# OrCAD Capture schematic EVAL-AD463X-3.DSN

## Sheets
1 PAGE1: size C; title: PRECISION SAR, DUAL ADC; rev: REV03; note: EVAL-AD463X_REV03; note: DIFFERENTIAL DUAL ADC
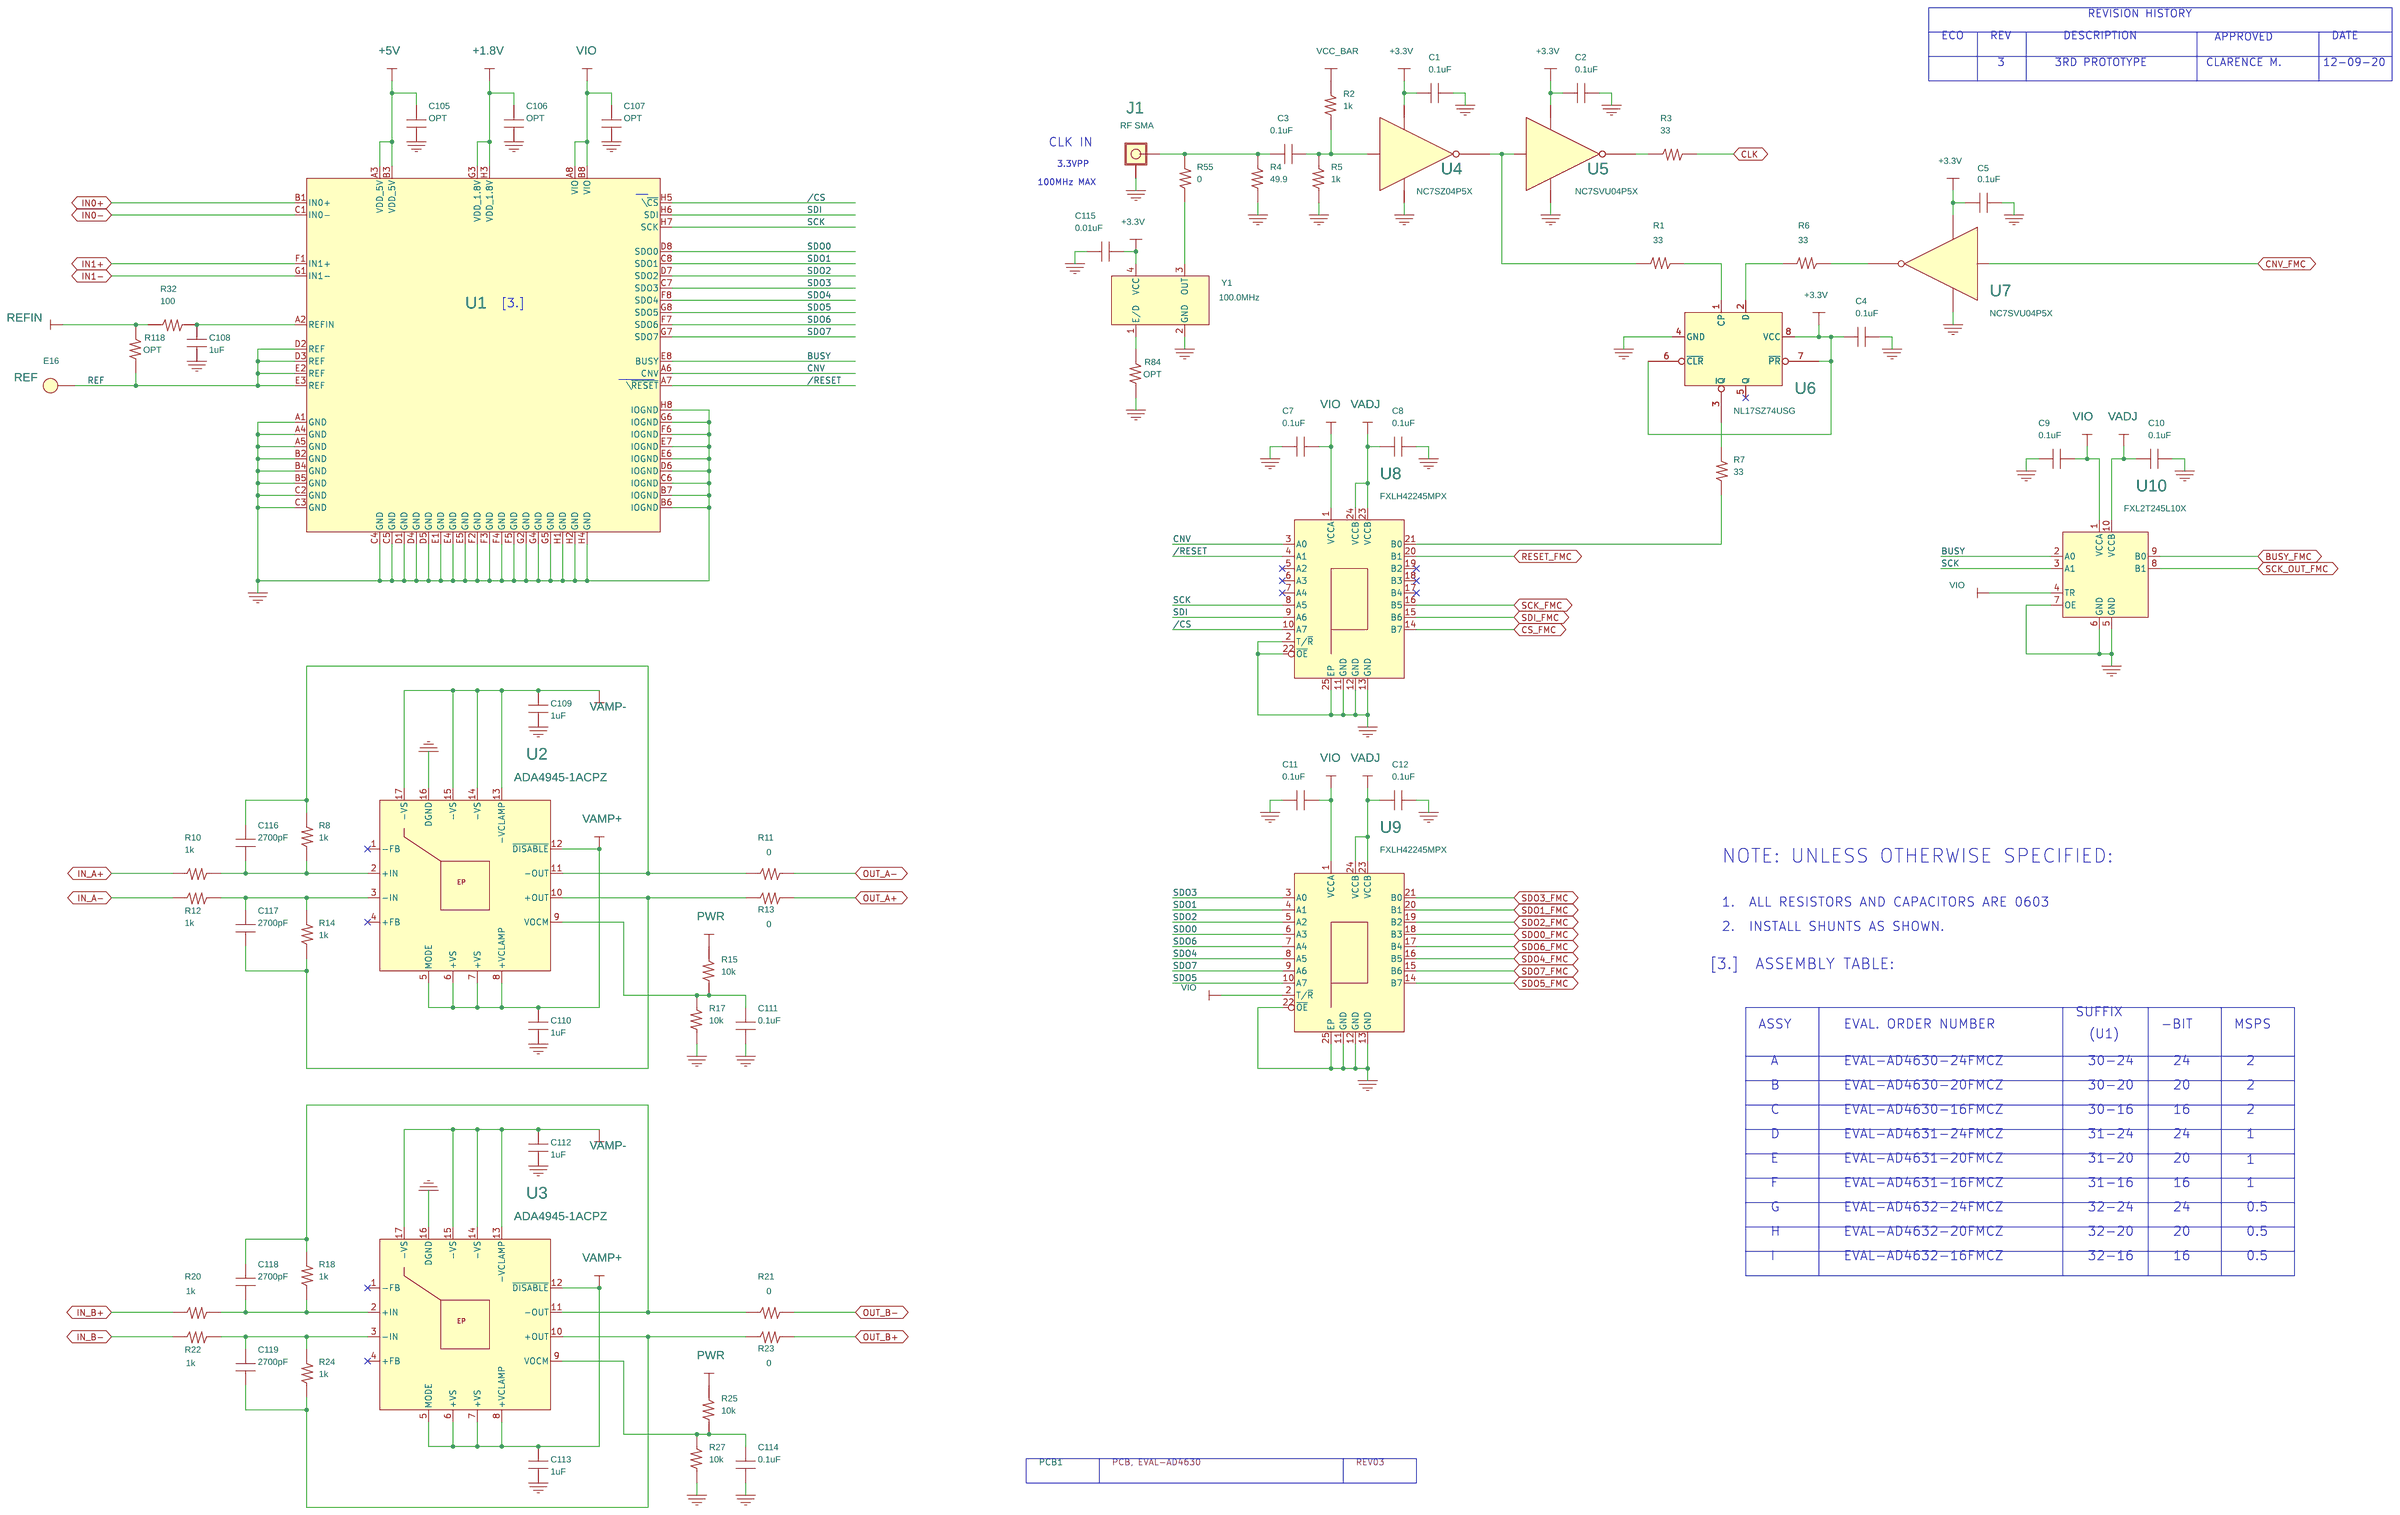
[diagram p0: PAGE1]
2 PAGE2: size B
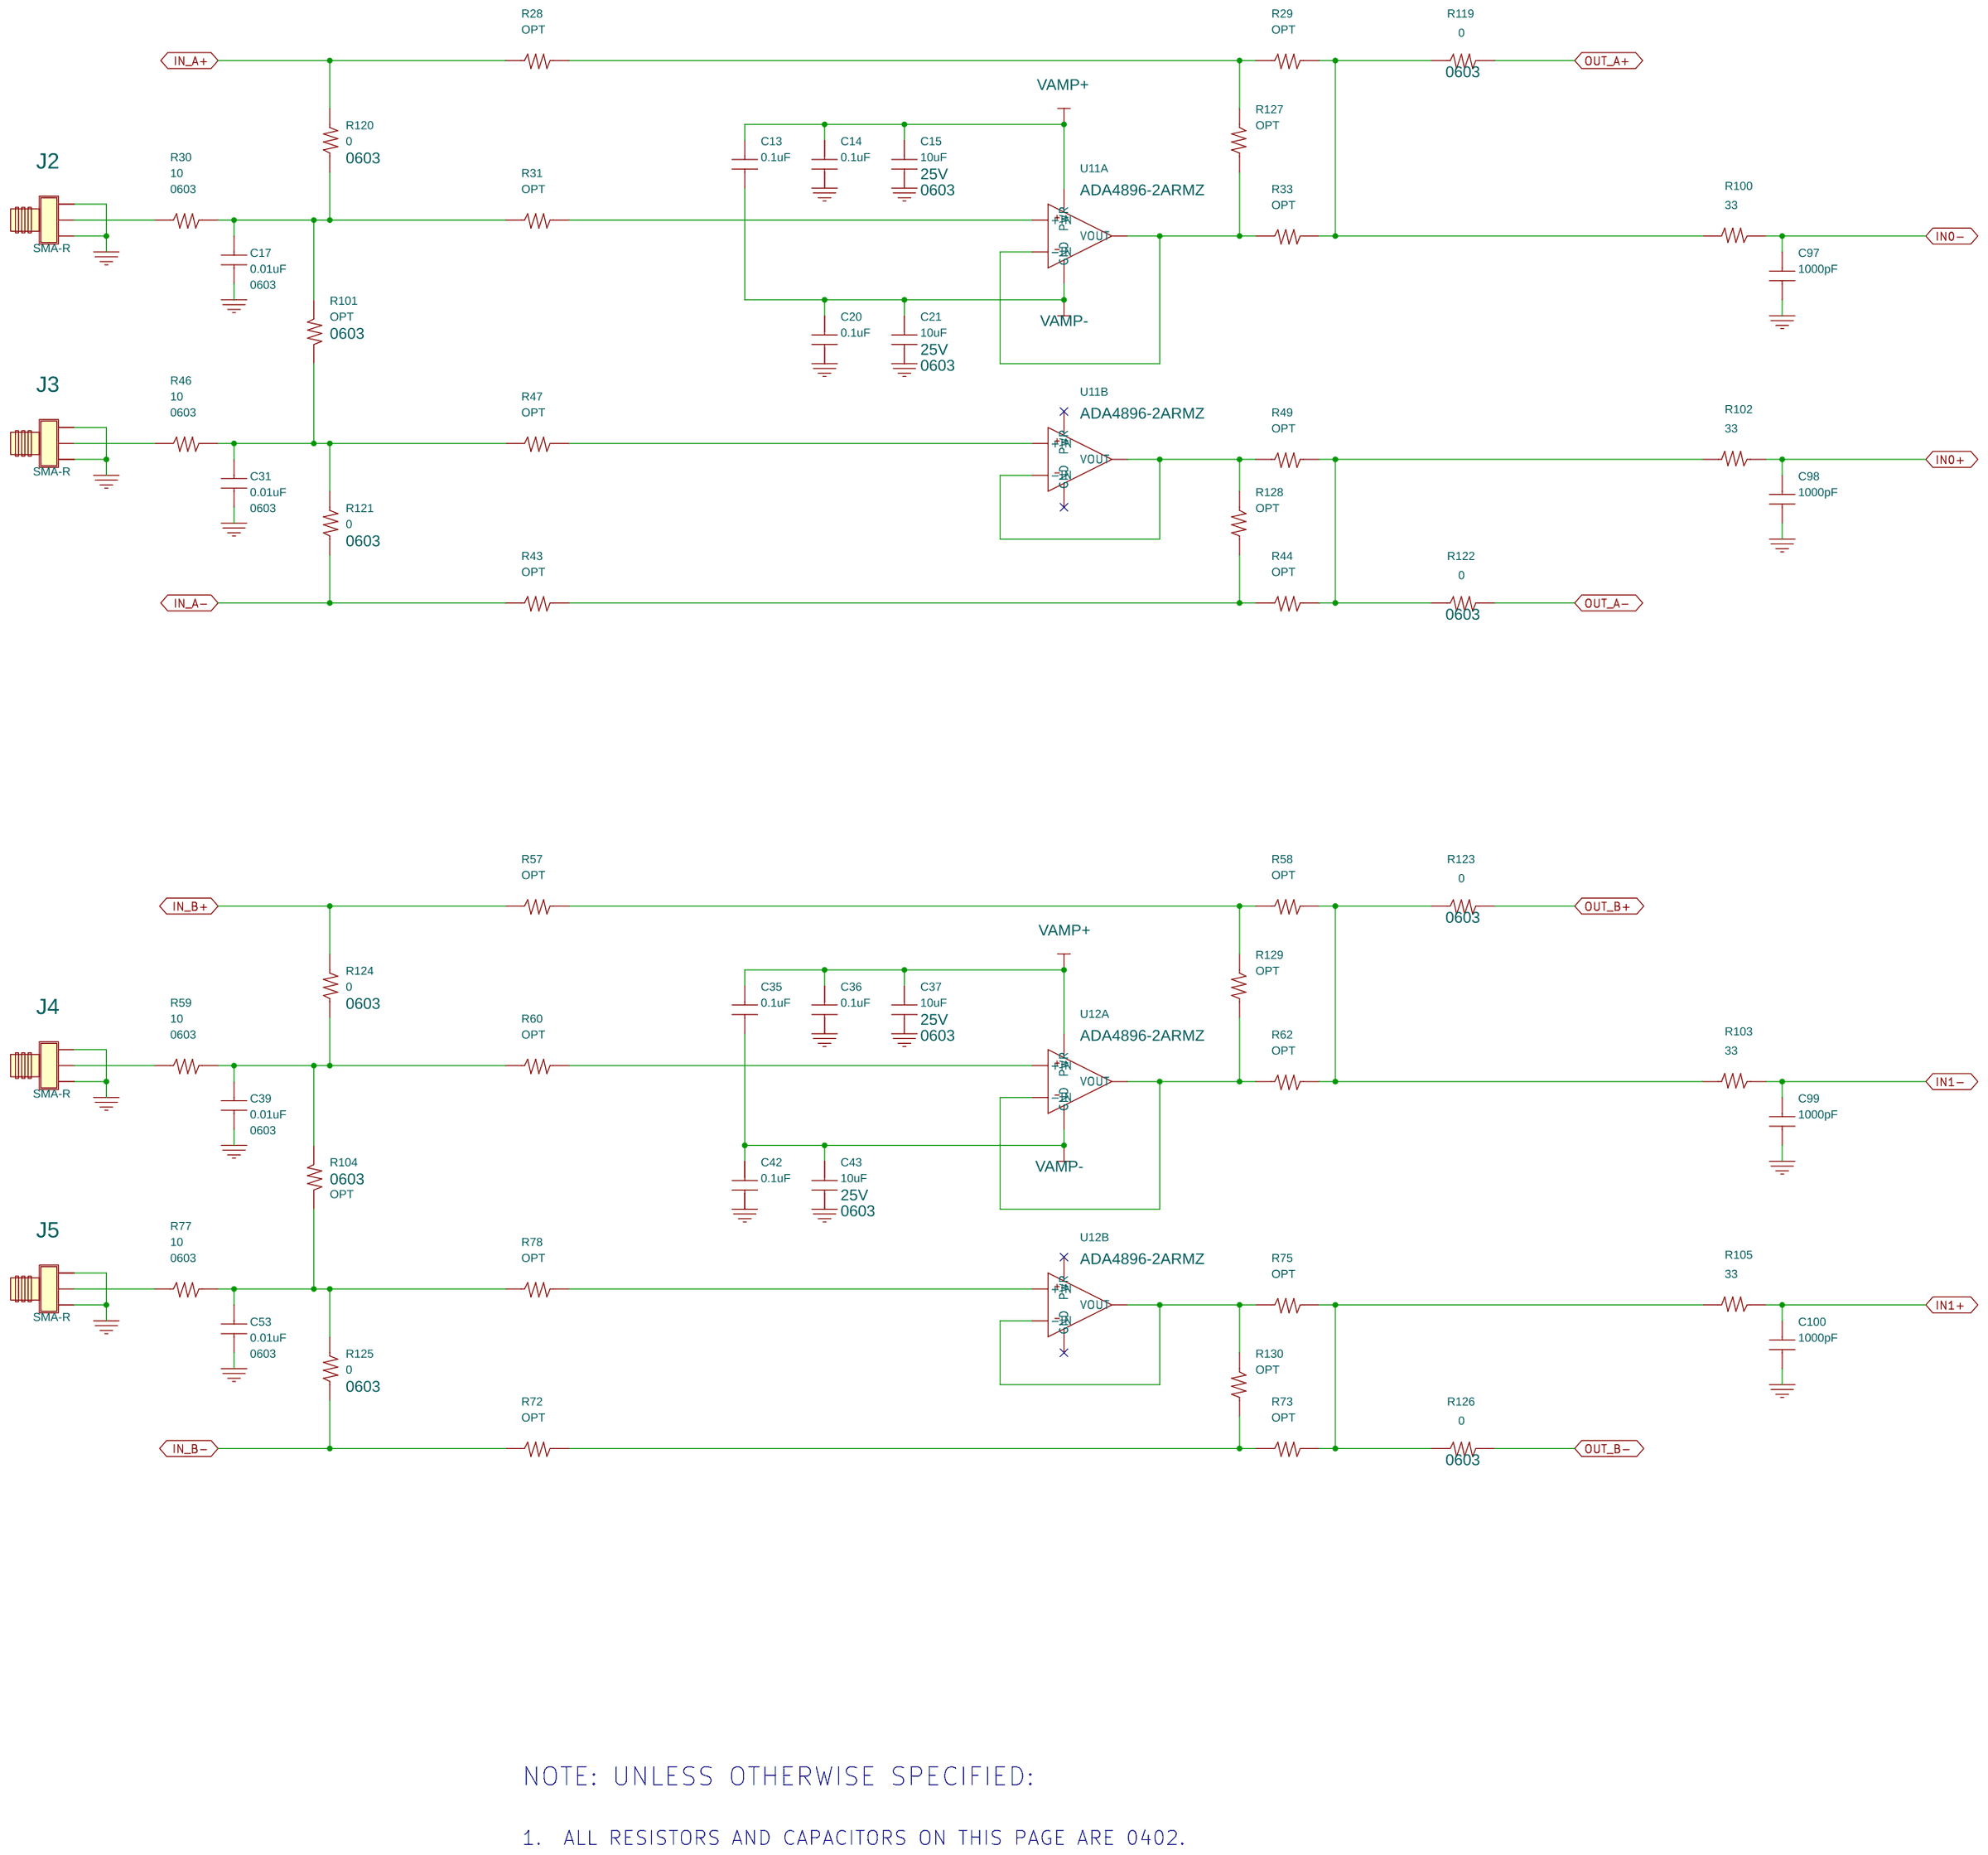
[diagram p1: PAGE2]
3 PAGE3: size C
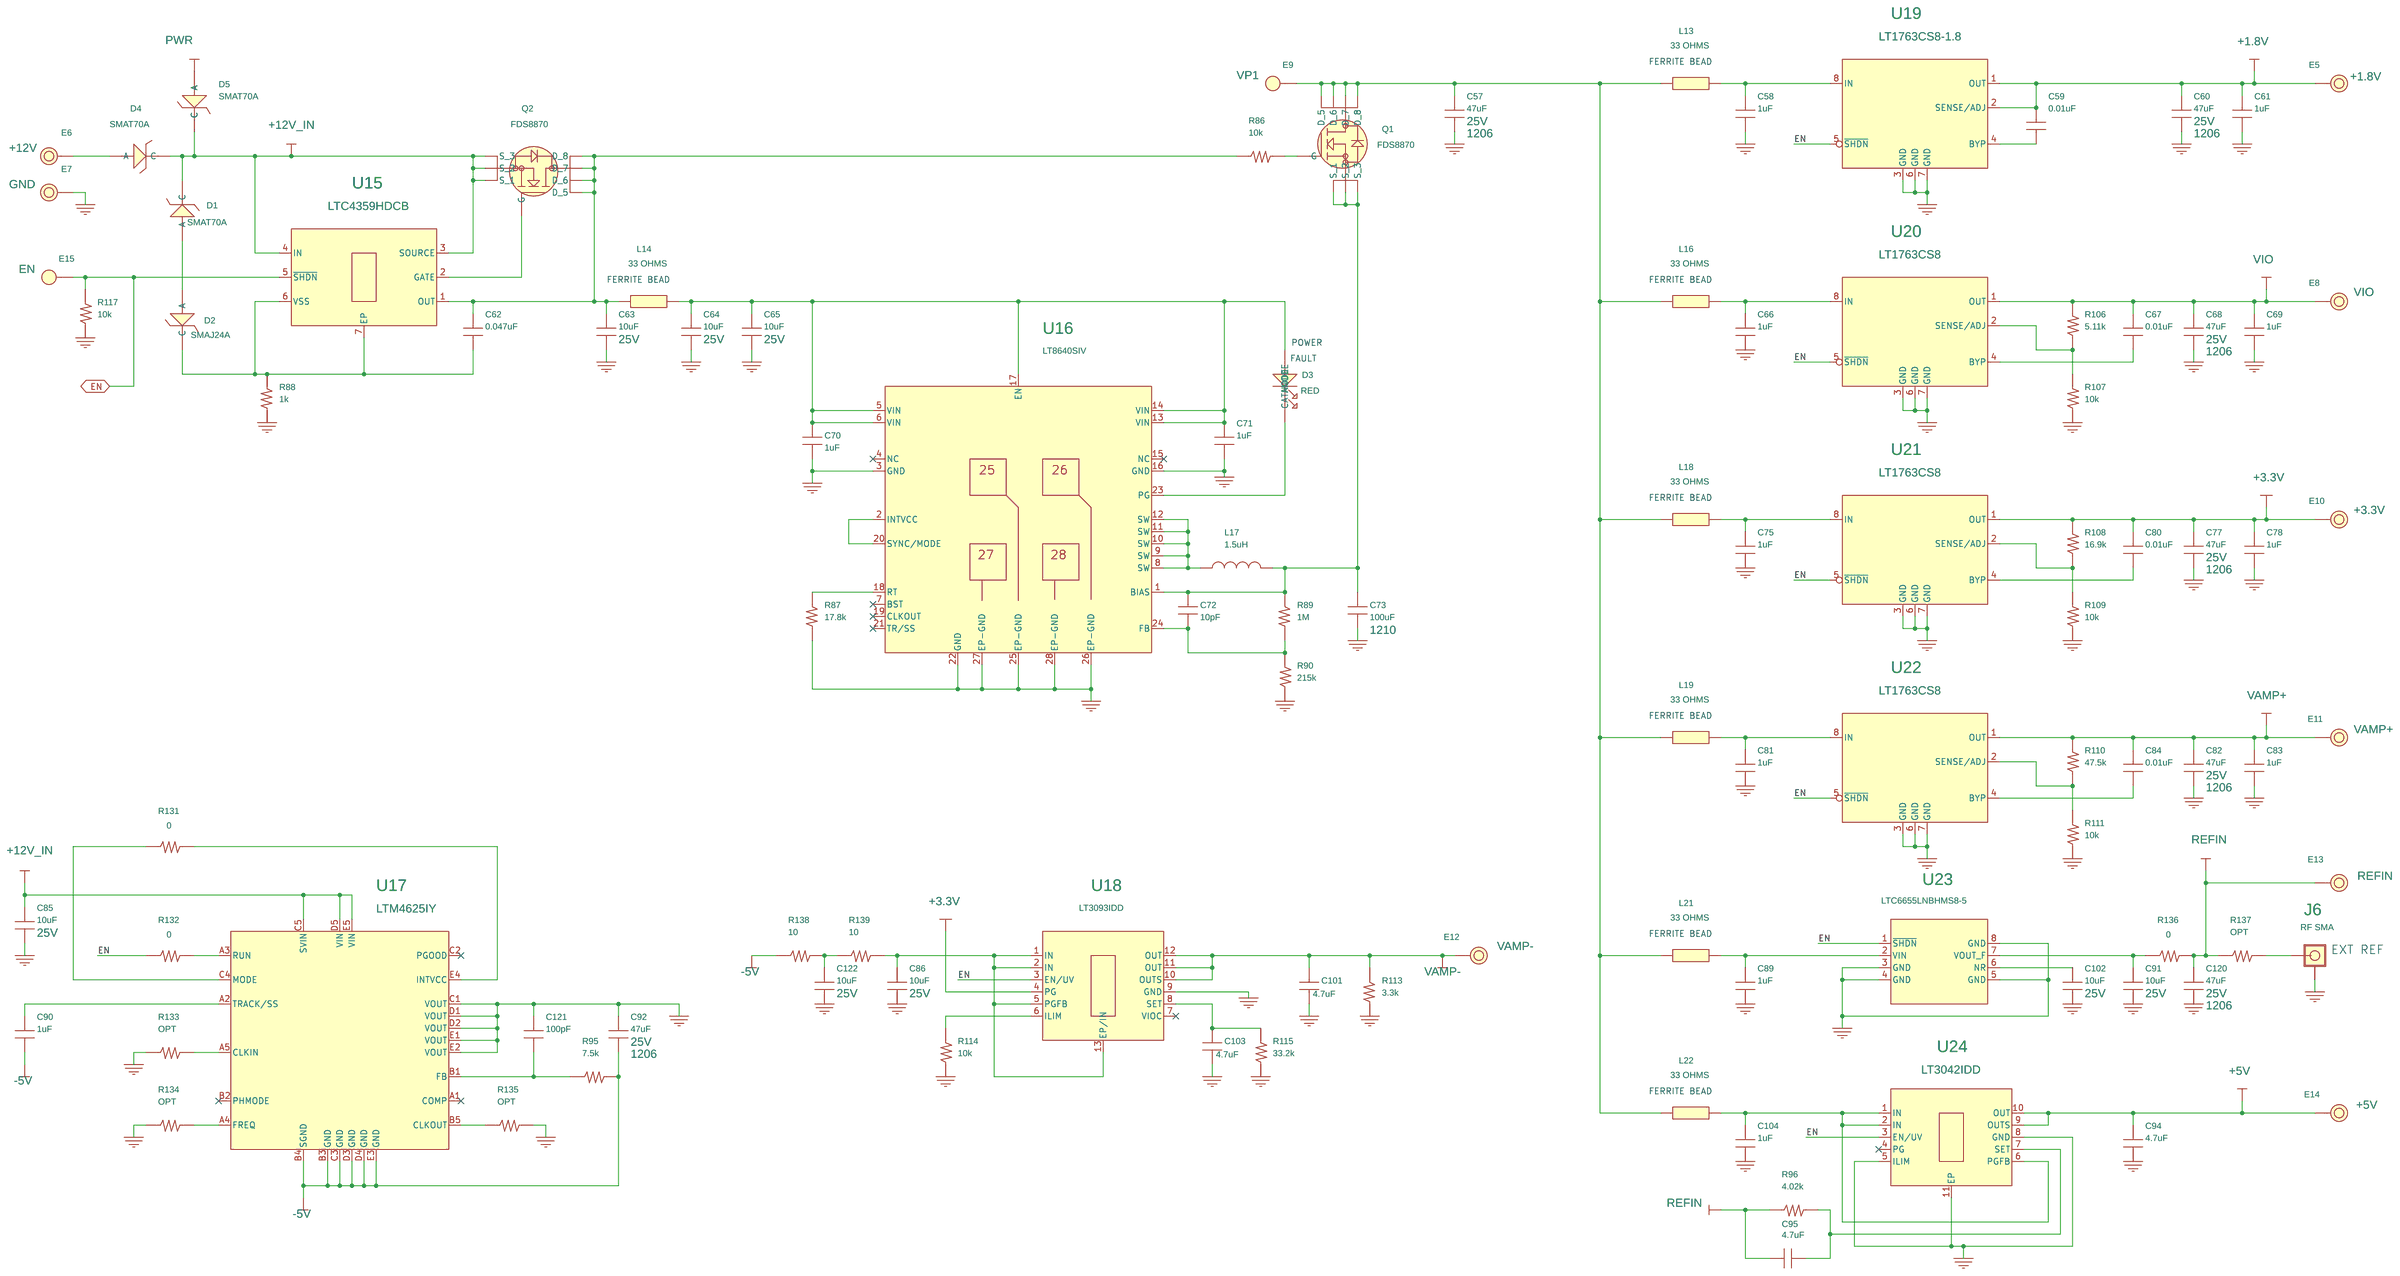
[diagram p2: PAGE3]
4 PAGE4: size B
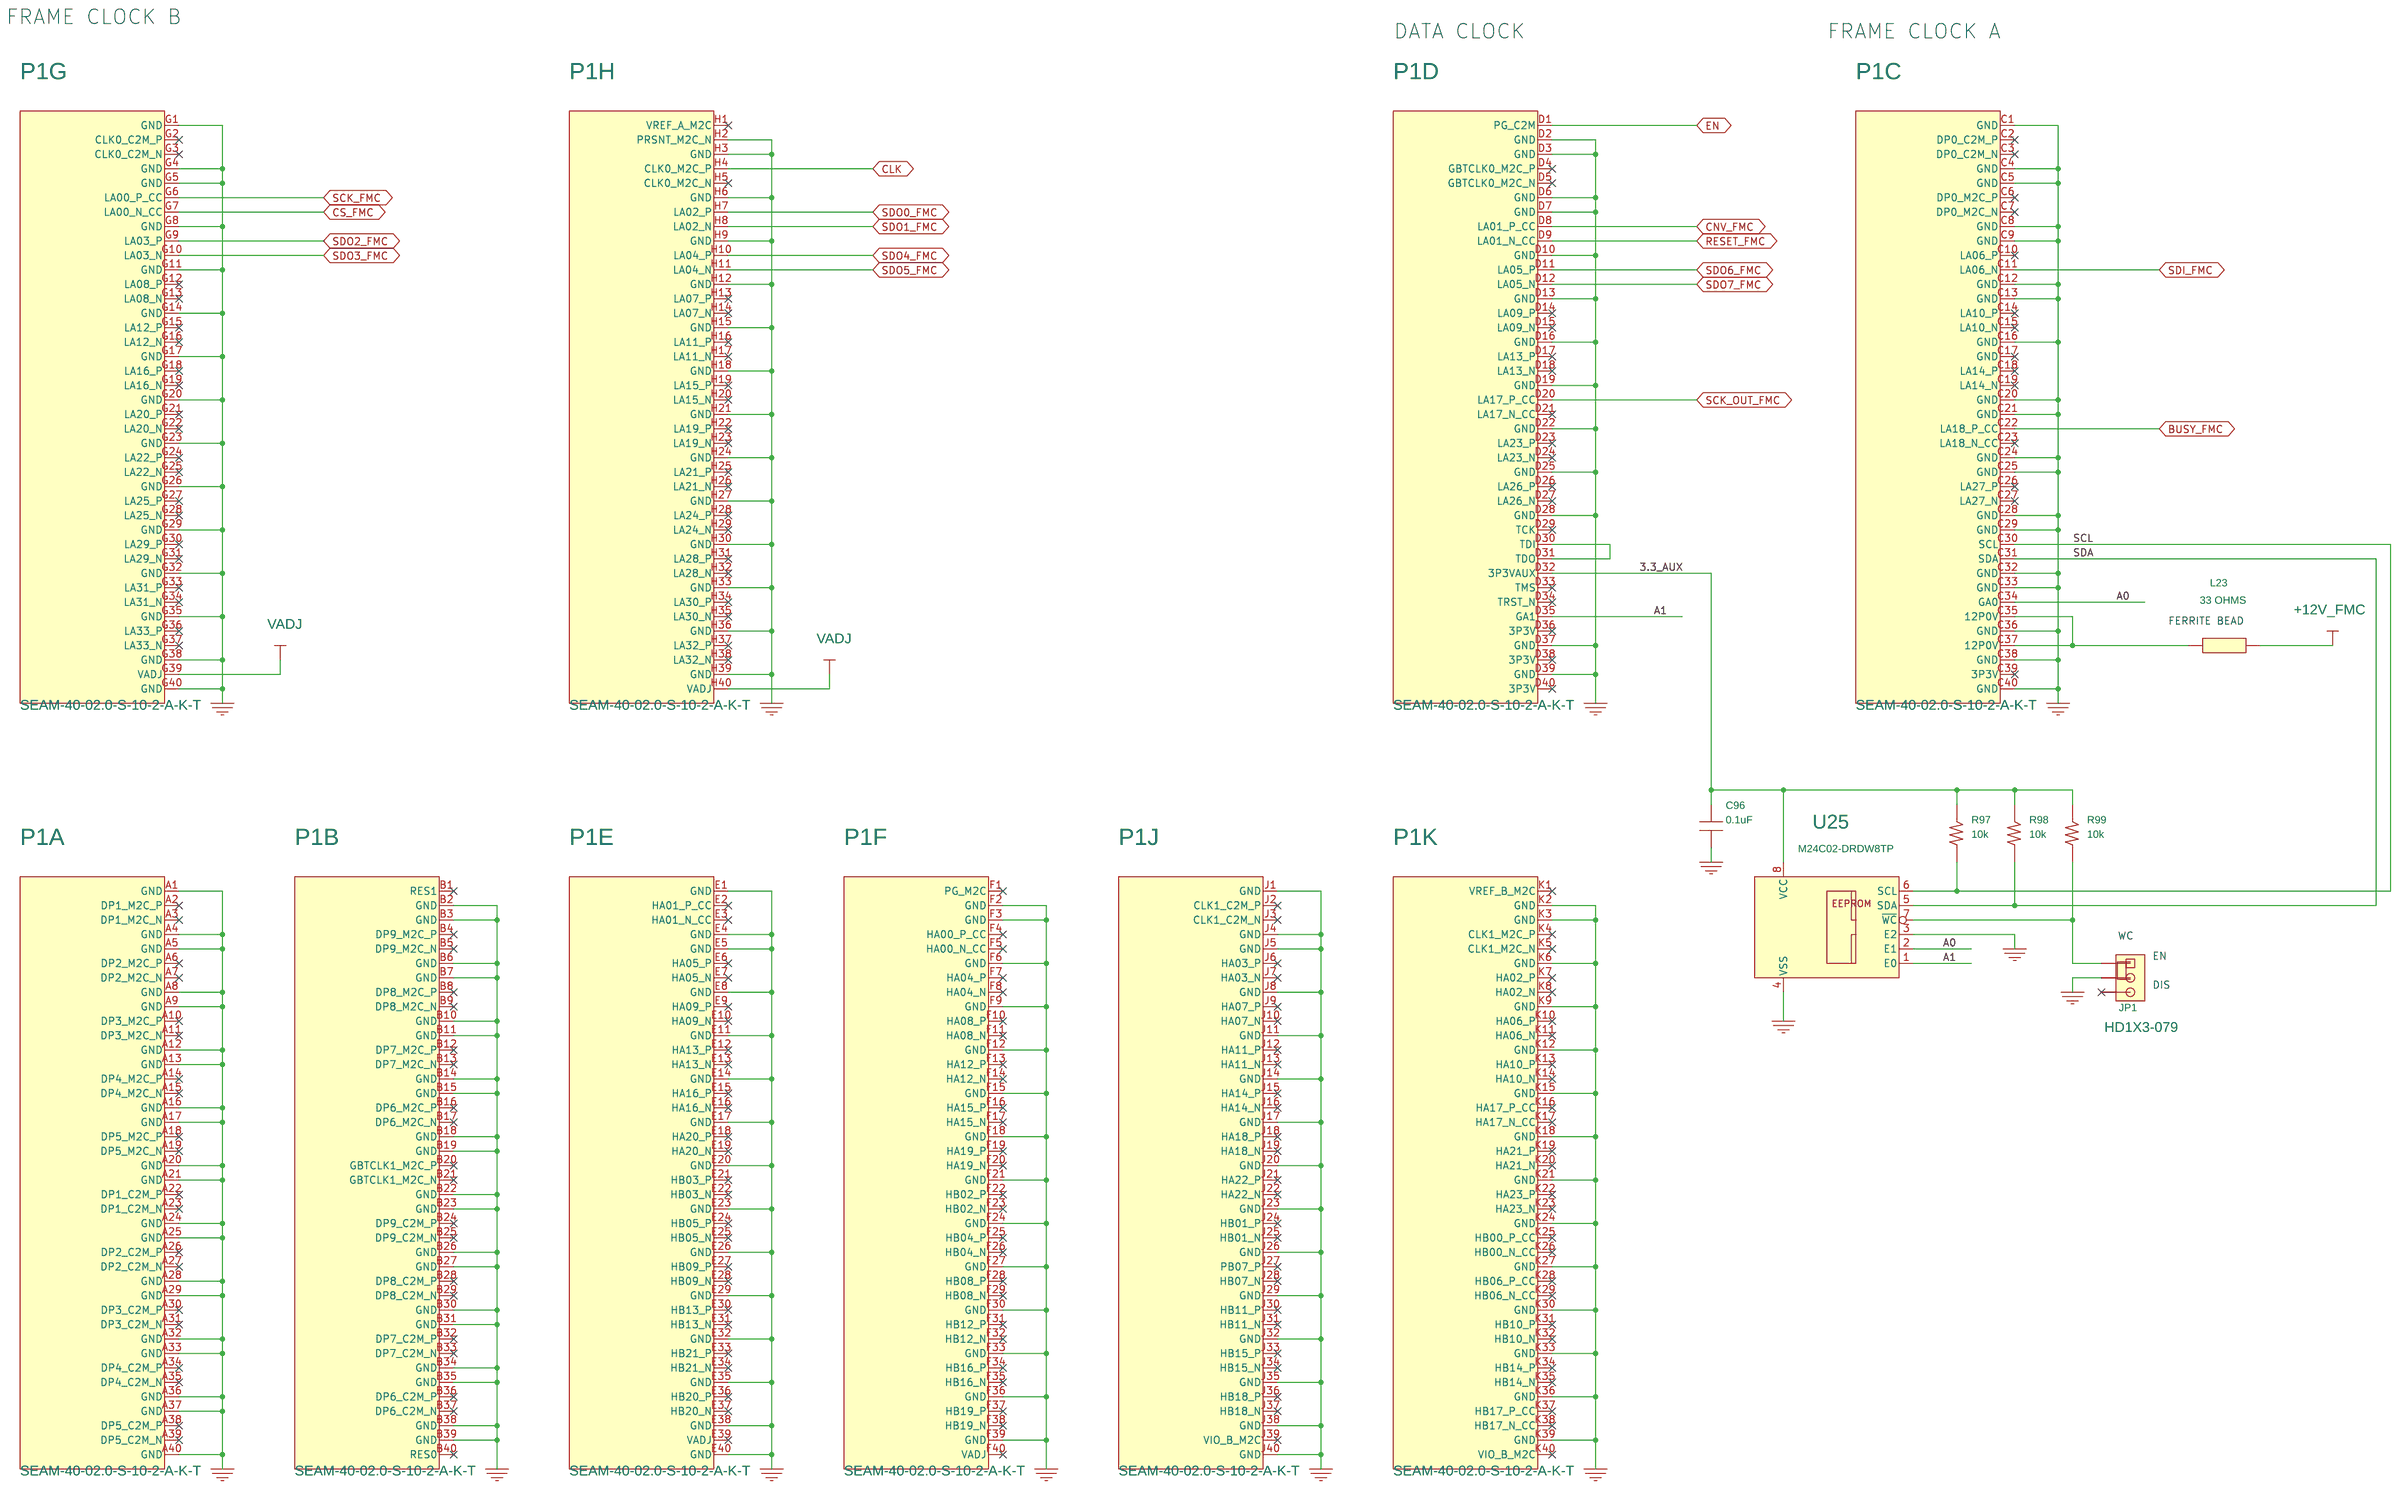
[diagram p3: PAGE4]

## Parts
sheet PAGE1
C1  0.1uF  [CC0603N]
C2  0.1uF  [CC0603N]
C3  0.1uF  [CC0603N]
C4  0.1uF  [CC0603N]
C5  0.1uF  [CC0603N]
C7  0.1uF  [CC0603N]
C8  0.1uF  [CC0603N]
C9  0.1uF  [CC0603N]
C10  0.1uF  [CC0603N]
C11  0.1uF  [CC0603N]
C12  0.1uF  [CC0603N]
C105  OPT  [CC0603N]
C106  OPT  [CC0603N]
C107  OPT  [CC0603N]
C108  1uF  [CC0603N]
C109  1uF  [CC0603N]
C110  1uF  [CC0603N]
C111  0.1uF  [CC0603N]
C112  1uF  [CC0603N]
C113  1uF  [CC0603N]
C114  0.1uF  [CC0603N]
C115  0.01uF  [CC0603N]
C116  2700pF  [CC0603N]
C117  2700pF  [CC0603N]
C118  2700pF  [CC0603N]
C119  2700pF  [CC0603N]
E16  TEST POINT  [MILLMAX2308]
J1  RF SMA  [AMPHENOL-132134]
PCB1  PCB, EVAL-AD4630
R1  33  [CR0603N]
R2  1k  [CR0603N]
R3  33  [CR0603N]
R4  49.9  [CR0603N]
R5  1k  [CR0603N]
R6  33  [CR0603N]
R7  33  [CR0603N]
R8  1k  [CR0603N]
R10  1k  [CR0603N]
R11  0  [CR0603N]
R12  1k  [CR0603N]
R13  0  [CR0603N]
R14  1k  [CR0603N]
R15  10k  [CR0603N]
R17  10k  [CR0603N]
R18  1k  [CR0603N]
R20  1k  [CR0603N]
R21  0  [CR0603N]
R22  1k  [CR0603N]
R23  0  [CR0603N]
R24  1k  [CR0603N]
R25  10k  [CR0603N]
R27  10k  [CR0603N]
R32  100  [CR0603N]
R55  0  [CR0603N]
R84  OPT  [CR0603N]
R118  OPT  [CR0603N]
U1  AD4630-24FMCZ  [LTC-BGA-64-1587]
U2  ADA4945-1  [ADI-CP-16-22]
U3  ADA4945-1  [ADI-CP-16-22]
U4  NC7SZ04P5X  [SC70-5]
U5  NC7SVU04P5X  [SC70-5]
U6  NL17SZ74USG  [ONSEMI-US8]
U7  NC7SVU04P5X  [SC70-5]
U8  FXLH42245MPX  [ONSEMI-MLP-24]
U9  FXLH42245MPX  [ONSEMI-MLP-24]
U10  FXL2T245L10X  [ONSEMI-MICROPAK-10]
Y1  100.0MHz  [CONNOR-WINFIELD-CWX813]
sheet PAGE2
C13  0.1uF  [CC0402N]
C14  0.1uF  [CC0402N]
C15  10uF  [CC0603N]
C17  0.01uF  [CC0603N]
C20  0.1uF  [CC0402N]
C21  10uF  [CC0603N]
C31  0.01uF  [CC0603N]
C35  0.1uF  [CC0402N]
C36  0.1uF  [CC0402N]
C37  10uF  [CC0603N]
C39  0.01uF  [CC0603N]
C42  0.1uF  [CC0402N]
C43  10uF  [CC0603N]
C53  0.01uF  [CC0603N]
C97  1000pF  [CC0402N]
C98  1000pF  [CC0402N]
C99  1000pF  [CC0402N]
C100  1000pF  [CC0402N]
J2  RF,SMA  [EMERSON_142-0701-851]
J3  RF,SMA  [EMERSON_142-0701-851]
J4  RF,SMA  [EMERSON_142-0701-851]
J5  RF,SMA  [EMERSON_142-0701-851]
R28  OPT  [CR0402N]
R29  OPT  [CR0402N]
R30  10  [CR0603N]
R31  OPT  [CR0402N]
R33  OPT  [CR0402N]
R43  OPT  [CR0402N]
R44  OPT  [CR0402N]
R46  10  [CR0603N]
R47  OPT  [CR0402N]
R49  OPT  [CR0402N]
R57  OPT  [CR0402N]
R58  OPT  [CR0402N]
R59  10  [CR0603N]
R60  OPT  [CR0402N]
R62  OPT  [CR0402N]
R72  OPT  [CR0402N]
R73  OPT  [CR0402N]
R75  OPT  [CR0402N]
R77  10  [CR0603N]
R78  OPT  [CR0402N]
R100  33  [CR0402N]
R101  OPT  [CR0603N]
R102  33  [CR0402N]
R103  33  [CR0402N]
R104  OPT  [CR0603N]
R105  33  [CR0402N]
R119  0  [CR0603N]
R120  0  [CR0603N]
R121  0  [CR0603N]
R122  0  [CR0603N]
R123  0  [CR0603N]
R124  0  [CR0603N]
R125  0  [CR0603N]
R126  0  [CR0603N]
R127  OPT  [CR0402N]
R128  OPT  [CR0402N]
R129  OPT  [CR0402N]
R130  OPT  [CR0402N]
U11  ADA4896-2ARMZ  [ADI-RM-8]  (sections A,B)
U12  ADA4896-2ARMZ  [ADI-RM-8]  (sections A,B)
sheet PAGE3
C57  47uF  [CC1206N]
C58  1uF  [CC0603N]
C59  0.01uF  [CC0603N]
C60  47uF  [CC1206N]
C61  1uF  [CC0603N]
C62  0.047uF  [CC0603N]
C63  10uF  [CC0603N]
C64  10uF  [CC0603N]
C65  10uF  [CC0603N]
C66  1uF  [CC0603N]
C67  0.01uF  [CC0603N]
C68  47uF  [CC1206N]
C69  1uF  [CC0603N]
C70  1uF  [CC0603N]
C71  1uF  [CC0603N]
C72  10pF  [CC0603N]
C73  100uF  [CC1210N]
C75  1uF  [CC0603N]
C77  47uF  [CC1206N]
C78  1uF  [CC0603N]
C80  0.01uF  [CC0603N]
C81  1uF  [CC0603N]
C82  47uF  [CC1206N]
C83  1uF  [CC0603N]
C84  0.01uF  [CC0603N]
C85  10uF  [CC0603N]
C86  10uF  [CC0603N]
C89  1uF  [CC0603N]
C90  1uF  [CC0603N]
C91  10uF  [CC0603N]
C92  47uF  [CC1206N]
C94  4.7uF  [CC0603N]
C95  4.7uF  [CC0603N]
C101  4.7uF  [CC0603N]
C102  10uF  [CC0603N]
C103  4.7uF  [CC0603N]
C104  1uF  [CC0603N]
C120  47uF  [CC1206N]
C121  100pF  [CC0603N]
C122  10uF  [CC0603N]
D1  SMAT70A  [SMA-N]
D2  SMAJ24A  [SMA-N]
D3  RED  [LED_0805]
D4  SMAT70A  [SMA-N]
D5  SMAT70A  [SMA-N]
E5  TEST POINT  [MILLMAX2501]
E6  TEST POINT  [MILLMAX2501]
E7  TEST POINT  [MILLMAX2501]
E8  TEST POINT  [MILLMAX2501]
E9  TEST POINT  [MILLMAX2308]
E10  TEST POINT  [MILLMAX2501]
E11  TEST POINT  [MILLMAX2501]
E12  TEST POINT  [MILLMAX2501]
E13  TEST POINT  [MILLMAX2501]
E14  TEST POINT  [MILLMAX2501]
E15  TEST POINT  [MILLMAX2308]
J6  RF SMA  [AMPHENOL-132134]
L13  33 OHMS@100MHz  [IND1206N]
L14  33 OHMS@100MHz  [IND1206N]
L16  33 OHMS@100MHz  [IND1206N]
L17  1.5uH  [COILCRAFT-XEL6030]
L18  33 OHMS@100MHz  [IND1206N]
L19  33 OHMS@100MHz  [IND1206N]
L21  33 OHMS@100MHz  [IND1206N]
L22  33 OHMS@100MHz  [IND1206N]
Q1  FDS8870  [SOIC-8N]
Q2  FDS8870  [SOIC-8N]
R86  10k  [CR0603N]
R87  17.8k  [CR0603N]
R88  1k  [CR0603N]
R89  1M  [CR0603N]
R90  215k  [CR0603N]
R95  7.5k  [CR0603N]
R96  4.02k  [CR0603N]
R106  5.11k  [CR0603N]
R107  10k  [CR0603N]
R108  16.9k  [CR0603N]
R109  10k  [CR0603N]
R110  47.5k  [CR0603N]
R111  10k  [CR0603N]
R113  3.3k  [CR0603N]
R114  10k  [CR0603N]
R115  33.2k  [CR0603N]
R117  10k  [CR0603N]
R131  0  [CR0603N]
R132  0  [CR0603N]
R133  OPT  [CR0603N]
R134  OPT  [CR0603N]
R135  OPT  [CR0603N]
R136  0  [CR0603N]
R137  OPT  [CR0603N]
R138  10  [CR0603N]
R139  10  [CR0603N]
U15  LTC4359-DCB  [LTC-DCB-6-1715]
U16  LT8640SIV  [LTC-LQFN-24-1511]
U17  LTM4625-BGA  [LTC-BGA-25-1905]
U18  LT3093IDD  [LTC-DD-12-1725]
U19  LT1763-S8-1.8  [LTC-S8-8-1610(S8)]
U20  LT1763-S8  [LTC-S8-8-1610(S8)]
U21  LT1763-S8  [LTC-S8-8-1610(S8)]
U22  LT1763-S8  [LTC-S8-8-1610(S8)]
U23  LTC6655LNBHMS8-5  [LTC-MS8-8-1660]
U24  LT3042-DD  [LTC-DD-10-1699]
sheet PAGE4
C96  0.1uF  [CC0603N]
JP1  HDR  [HD1X3-079]
L23  33 OHMS@100MHz  [IND1206N]
P1  BGA SOCKET  [SAMTEC-SEAM-40-02.0-S-10-2-A-K]  (sections A,B,C,D,E,F,G,H,J,K)
R97  10k  [CR0603N]
R98  10k  [CR0603N]
R99  10k  [CR0603N]
U25  M24C02-DRDW8TP  [STMICRO-TSSOP8]
XJP1  SHUNT

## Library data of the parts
C1-C5 C7-C12 C96 C111 C114 = CAP_ALT: CAP.,0.1uF,X7R,50V,10%,0603; CLASS: DISCRETE; Dielectric Type: X7R; FPLIST: CC0603N,CC0603L,CC0603M; Inventory Qty: 32511; Manufacturer: AVX; Manufacturer PN: 06035C104KAT2A; PART_NUMBER: 150-0102; Package Size: 0603; Rated Voltage: 50V; Tolerance: 10%
C105-C107 = CAP_ALT: CAP., OPTION, 0603; CLASS: DISCRETE; FPLIST: CC0603N,CC0603L,CC0603M; PART_NUMBER: 150-3038; Package Size: 0603; Package Type: SMD
C58 C61 C66 C69-C71 C75 C78 C81 C83 C89 C90 C104 C108-C110 C112 C113 = CAP_ALT: CAP.,1uF,X5R,25V,20%,0603; CLASS: DISCRETE; Dielectric Type: X5R; FPLIST: CC0603N,CC0603L,CC0603M; Inventory Qty: 13096; Manufacturer: AVX; Manufacturer PN: 06033D105MAT2A; PART_NUMBER: 150-0187; Package Size: 0603; Rated Voltage: 25V; Tolerance: 20%
C59 C67 C80 C84 C115 = CAP_ALT: CAP.,0.01uF,X7R,50V,10%,0603; CLASS: DISCRETE; Dielectric Type: X7R; FPLIST: CC0603N,CC0603L,CC0603M; Inventory Qty: 28483; Manufacturer: AVX; Manufacturer PN: 06035C103KAT2A; PART_NUMBER: 150-0002; Package Size: 0603; Rated Voltage: 50V; Tolerance: 10%
C116-C119 = CAP_ALT: CAP.,2700pF,C0G,50V,5%,0603; CLASS: DISCRETE; Dielectric Type: C0G; FPLIST: CC0603N,CC0603L,CC0603M; Inventory Qty: 0; Manufacturer: NIC; Manufacturer PN: NMC0603NPO272J50TRPF; PART_NUMBER: 150-0202; Package Size: 0603; Rated Voltage: 50V; Tolerance: 5%
E16 = TEST_POINT_.156_MILL-MAX_2308: TEST POINT,TURRET,0.064" MTG. HOLE,PCB 0.062" THK; 1ST PART FIELD: REF; CLASS: IO; Inventory Qty: 913405; Manufacturer: MILL-MAX; Manufacturer PN: 2308-2-00-80-00-00-07-0; PART_NUMBER: 260-0004
J1 J6 = SMA_ALT2: CONN.,RF SMA,JACK,THT, STR,50 OHMS; CLASS: IO; Inventory Qty: 2450; Manufacturer: AMPHENOL RF; Manufacturer PN: 132134; PART_NUMBER: 250-0472
PCB1 = BLANK_PCB_PART: BOM Notes: REV03; CLASS: DISCRETE; Inventory Qty: 0; Manufacturer: ADI APPROVED SUPPLIER; Manufacturer PN: 600-EVAL-AD4630; PART_NUMBER: 600-EVAL-AD4630
R1 R3 R6 R7 = RES_ALT: RES.,33 OHMS,1%,1/10W,0603,AEC-Q200; CLASS: DISCRETE; FPLIST: CR0603N,CR0603L,CR0603M; Inventory Qty: 18395; Manufacturer: NIC; Manufacturer PN: NRC06F33R0TRF; PART_NUMBER: 100-2805; Package Size: 0603; Rated Power: 1/10W; Temperature Coefficient: 100ppm/C; Tolerance: 1%
R2 R5 R8 R10 R12 R14 R18 R20 R22 R24 R88 = RES_ALT: RES.,1k OHMS,0.1%,1/10W,0603; CLASS: DISCRETE; FPLIST: CR0603N,CR0603L,CR0603M; Inventory Qty: 4960; Manufacturer: YAGEO; Manufacturer PN: RT0603BRD071KL; PART_NUMBER: 100-1645; Package Size: 0603; Rated Power: 1/10W; Temperature Coefficient: +/-25ppm; Tolerance: 0.1%
R4 = RES_ALT: RES.,49.9 OHMS,1%,1/10W,0603,AEC-Q200; CLASS: DISCRETE; FPLIST: CR0603N,CR0603L,CR0603M; Inventory Qty: 93236; Manufacturer: VISHAY; Manufacturer PN: CRCW060349R9FKEA; PART_NUMBER: 100-0167; Package Size: 0603; Rated Power: 1/10W; Temperature Coefficient: 100ppm; Tolerance: 1%
R11 R13 R21 R23 R55 R119-R126 R131 R132 R136 = RES_ALT: RES.,0 OHM,1/10W,0603,AEC-Q200; CLASS: DISCRETE; FPLIST: CR0603N,CR0603L,CR0603M; Inventory Qty: 701066; Manufacturer: VISHAY; Manufacturer PN: CRCW06030000Z0EA; PART_NUMBER: 100-0009; Package Size: 0603; Rated Power: 1/10W
R15 R17 R25 R27 R86 R97-R99 R107 R109 R111 R114 R117 = RES_ALT: RES.,10k OHMS,1%,1/10W,0603,AEC-Q200,NO SUBS. ALLOWED; CLASS: DISCRETE; FPLIST: CR0603N,CR0603L,CR0603M; Inventory Qty: 39360; Manufacturer: VISHAY; Manufacturer PN: CRCW060310K0FKEA; PART_NUMBER: 100-1059; Package Size: 0603; Rated Power: 1/10W; Temperature Coefficient: +/-100PPM; Tolerance: 1%
R32 = RES_ALT: RES.,100 OHMS,1%,1/10W,0603; CLASS: DISCRETE; FPLIST: CR0603N,CR0603L,CR0603M; Inventory Qty: 70604; Manufacturer: YAGEO; Manufacturer PN: RC0603FR-07100RL; PART_NUMBER: 100-0150; Package Size: 0603; Rated Power: 1/10W; Temperature Coefficient: 100ppm/C; Tolerance: 1%
R84 R101 R104 R118 R133-R135 R137 = RES_ALT: RES., OPTION, 0603; CLASS: DISCRETE; FPLIST: CR0603N,CR0603L,CR0603M; PART_NUMBER: 100-2374; Package Size: 0603
U1 = AD463X-XXFMCZ-BGA64-7X7-1.34: PRECISION SAR, DIFF. DUAL ADC,BGA64-7X7X1.34; CLASS: IC; Inventory Qty: 5; Manufacturer: ANALOG DEVICES; Manufacturer PN: AD4630-24FMCZ-R; Package Type: 64-pin BGA 7 X 7 X1.34mm
U2 U3 = ADA4945-1-LFCSP16-3X3: IC,DIFFERENTIAL ADC DRIVER,LFCSP16-3X3; CLASS: IC; Inventory Qty: 0; Manufacturer: ANALOG DEVICES; Manufacturer PN: ADA4945-1ACPZ; PART_NUMBER: ADA4945-1ACPZ; Package Type: LFCSP16-3X3
U4 = NC7SZ04P5X-SC70-5: IC,TinyLogic UHS Inverter,SC70-5; CLASS: IC; Inventory Qty: 7420; Manufacturer: FAIRCHILD SEMI; PART_NUMBER: 280-0495
U5 U7 = NC7SVU04P5X-SC70-5: IC,ULP-A UNBUFFERED INVERTER,SC70-5; CLASS: IC; Inventory Qty: 10185; Manufacturer: ON SEMICONDUCTOR; PART_NUMBER: 280-0491
U6 = NL17SZ74-US8: IC,Single D Flip Flop,US8,Case 493; CLASS: IC; Inventory Qty: 15209; Manufacturer: ON SEMICONDUCTOR; PART_NUMBER: 280-0490; Package Size: US8; Package Type: US8
U8 U9 = FXLH42245MPX-MLP24-3.5X4.5: IC,DUAL VOLTAGE SUPPLY TRANSLATOR,MLP24-3.5X4.5,8-Bit; CLASS: IC; Inventory Qty: 700; Manufacturer: ON SEMICONDUCTOR; PART_NUMBER: 280-0541; Package Type: MLP24-3.5X4.5
U10 = FXL2T245-MICROPAK-10: IC,DUAL VOLTAGE SUPPLY TRANSLATOR,MICROPAK-10; CLASS: IC; Inventory Qty: 0; Manufacturer: ON SEMICONDUCTOR; PART_NUMBER: 280-0713; Package Type: MICROPAK-10
Y1 = Y-CWX813: CRYSTAL,CLOCK OSCILLATOR,100.0MHz,15pF,+/-25ppm,SMD 5x7mm,3.3V,LVCMOS,Y-CWX813; CLASS: DISCRETE; Frequency Stability: +/-25ppm; Inventory Qty: 0; Manufacturer: CONNOR WINFIELD; Manufacturer PN: CWX813-100.0M; PART_NUMBER: 340-0221
C13 C14 C20 C35 C36 C42 = CAP_ALT: CAP.,0.1uF,X7R,50V,10%,0402,AEC-Q200; CLASS: DISCRETE; Dielectric Type: X7R; FPLIST: CC0402N,CC0402L,CC0402M; Inventory Qty: 75030; Manufacturer: MURATA; Manufacturer PN: GCM155R71H104KE02D; PART_NUMBER: 150-2620; Package Size: 0402; Rated Voltage: 50V; Temperature Coefficient: X7R; Tolerance: 10%
C15 C21 C37 C43 C63-C65 C85 C86 C91 C102 C122 = CAP_ALT: CAP.,10uF,X5R,25V,20%,0603,NO SUBS. ALLOWED; CLASS: DISCRETE; Dielectric Type: X5R; FPLIST: CC0603N,CC0603L,CC0603M; Inventory Qty: 18142; Manufacturer: MURATA; Manufacturer PN: GRM188R61E106MA73D; PART_NUMBER: 150-2347; Package Size: 0603; Rated Voltage: 25V; Tolerance: 20%
C17 C31 C39 C53 = CAP_ALT: CAP.,0.01uF,C0G,25V,5%,0603; CLASS: DISCRETE; Dielectric Type: C0G; FPLIST: CC0603N,CC0603L,CC0603M; Inventory Qty: 18308; Manufacturer: KEMET; Manufacturer PN: C0603C103J3GACTU; PART_NUMBER: 150-2101; Package Size: 0603; Package Type: SMD; Rated Voltage: 25V; Tolerance: 5%
C97-C100 = CAP_ALT: CAP.,1000pF,C0G,50V,5%,0402; CLASS: DISCRETE; Dielectric Type: C0G; FPLIST: CC0402N,CC0402L,CC0402M; Inventory Qty: 6987; Manufacturer: MURATA; Manufacturer PN: GRM1555C1H102JA01D; PART_NUMBER: 150-2022; Package Size: 0402; Rated Voltage: 50V; Tolerance: 5%
J2-J5 = CONN_SMA_5PIN_ALT: CONN.,RF,SMA,JACK,FEMALE,RCPT,END LAUNCH,ST,50 OHM,TAB CT,Au; CLASS: IO; Inventory Qty: 26233; Manufacturer: CINCH/ BEL; Manufacturer PN: 142-0701-851; PART: SMA-R; PART_NUMBER: 250-0446
R28 R29 R31 R33 R43 R44 R47 R49 R57 R58 R60 R62 R72 R73 R75 R78 R127-R130 = RES_ALT: RES., OPTION, 0402; CLASS: DISCRETE; FPLIST: CR0402N,CR0402L,CR0402M; PART_NUMBER: 100-0357; Package Size: 0402
R30 R46 R59 R77 R138 R139 = RES_ALT: RES.,10 OHMS,5%,1/10W,0603,AEC-Q200; CLASS: DISCRETE; FPLIST: CR0603N,CR0603L,CR0603M; Inventory Qty: 87824; Manufacturer: VISHAY; Manufacturer PN: CRCW060310R0JNEA; PART_NUMBER: 100-2744; Package Size: 0603; Rated Power: 1/10W; Temperature Coefficient: +/-200ppm; Tolerance: 5%
R100 R102 R103 R105 = RES_ALT: RES.,33 OHMS,5%,1/16W,0402,AEC-Q200; CLASS: DISCRETE; FPLIST: CR0402N,CR0402L,CR0402M; Inventory Qty: 188185; Manufacturer: NIC; Manufacturer PN: NRC04J330TRF; PART_NUMBER: 100-2624; Package Size: 0402; Rated Power: 1/16W; Temperature Coefficient: 200ppm; Tolerance: 5%
U11 U12 = ADA4896-2ARMZ-MS8: IC,RAIL-TO-RAIL OUTPUT AMPLIFIERS,MSOP-8L; CLASS: IC; Inventory Qty: 0; Manufacturer: ANALOG DEVICES; Package Type: MSOP-8L
C57 C60 C68 C77 C82 C92 C120 = CAP_ALT: CAP.,47uF,X5R,25V,20%,1206; CLASS: DISCRETE; Dielectric Type: X5R; FPLIST: CC1206N,CC1206L,CC1206M; Inventory Qty: 6633; Manufacturer: MURATA; Manufacturer PN: GRM31CR61E476ME44L; PART_NUMBER: 150-0270; Package Size: 1206; Rated Voltage: 25V; Tolerance: 20%
C62 = CAP_ALT: CAP.,0.047uF,X7R,50V,10%,0603; CLASS: DISCRETE; Dielectric Type: X7R; FPLIST: CC0603N,CC0603L,CC0603M; Inventory Qty: 19580; Manufacturer: AVX; Manufacturer PN: 06035C473KAT2A; PART_NUMBER: 150-0097; Package Size: 0603; Rated Voltage: 50V; Tolerance: 10%
C72 = CAP_ALT: CAP.,10pF,C0G,50V,+/-0.25pF,0603; CLASS: DISCRETE; Dielectric Type: C0G; FPLIST: CC0603N,CC0603L,CC0603M; Inventory Qty: 35764; Manufacturer: TDK; Manufacturer PN: C1608C0G1H100C080AA; PART_NUMBER: 150-3516; Package Size: 0603; Rated Voltage: 50V; Tolerance: +/-0.25pF
C73 = CAP_ALT: CAP.,100uF,X5R,16V,20%,1210; CLASS: DISCRETE; Dielectric Type: X5R; FPLIST: CC1210N,CC1210L,CC1210M; Inventory Qty: 2932; Manufacturer: AVX; Manufacturer PN: 1210YD107MAT2A; PART_NUMBER: 150-3238; Package Size: 1210; Package Type: SMD; Rated Voltage: 16V; Tolerance: 20%
C94 C95 C101 C103 = CAP_ALT: CAP.,4.7uF,X6S,25V,10%,0603; CLASS: DISCRETE; Dielectric Type: X6S; FPLIST: CC0603N,CC0603L,CC0603M; Inventory Qty: 0; Manufacturer: MURATA; Manufacturer PN: GRM188C81E475KE11D; PART_NUMBER: 150-0798; Package Size: 0603; Rated Voltage: 25V; Tolerance: 10%
C121 = CAP_ALT: CAP.,100pF,C0G,50V,10%,0603; CLASS: DISCRETE; Dielectric Type: C0G; FPLIST: CC0603N,CC0603L,CC0603M; Inventory Qty: 24924; Manufacturer: AVX; Manufacturer PN: 06035A101KAT2A; PART_NUMBER: 150-3134; Package Size: 0603; Rated Voltage: 50V; Tolerance: 10%
D1 D4 D5 = DIODE_TVS_B: DIODE,TVS,70V,400W,SMA; CLASS: DISCRETE; FPLIST: SMA-N,SMA-L,SMA-M,SMA; Inventory Qty: 5409; Manufacturer: DIODES INC.; Manufacturer PN: SMAT70A-13-F; Max Forward Current or Rated Power: 400W; PART_NUMBER: 210-0163; Package Size: SMA; Package Type: SMA; Rated Voltage or Zener Voltage: 70V
D2 = DIODE_TVS_B: DIODE,TVS,UNI-DIRECT,24V,400W,SMA; CLASS: DISCRETE; FPLIST: SMA-N,SMA-L,SMA-M,SMA; Inventory Qty: 3198; Manufacturer: DIODES INC.; Manufacturer PN: SMAJ24A-13-F; Max Forward Current or Rated Power: 400W; PART_NUMBER: 210-0121; Package Size: SMA; Package Type: SMA; Rated Voltage or Zener Voltage: 24V
D3 = LED: LED,RED,WATER-CLEAR,0805; CLASS: DISCRETE; Inventory Qty: 13468; Manufacturer: WURTH ELEKTRONIK; Manufacturer PN: 150080RS75000; PART_NUMBER: 270-0081; Package Type: 0805
E5 = TESTPOINT_.219_MILL-MAX_2501: TEST POINT,TURRET,0.094" MTG. HOLE,PCB 0.062" THK; 1: +1.8V; CLASS: IO; Inventory Qty: 830610; Manufacturer: MILL-MAX; Manufacturer PN: 2501-2-00-80-00-00-07-0; PART_NUMBER: 260-0003
E6 = TESTPOINT_.219_MILL-MAX_2501: TEST POINT,TURRET,0.094" MTG. HOLE,PCB 0.062" THK; 1: +12V; CLASS: IO; Inventory Qty: 830610; Manufacturer: MILL-MAX; Manufacturer PN: 2501-2-00-80-00-00-07-0; PART_NUMBER: 260-0003
E7 = TESTPOINT_.219_MILL-MAX_2501: TEST POINT,TURRET,0.094" MTG. HOLE,PCB 0.062" THK; 1: GND; CLASS: IO; Inventory Qty: 830610; Manufacturer: MILL-MAX; Manufacturer PN: 2501-2-00-80-00-00-07-0; PART_NUMBER: 260-0003
E8 = TESTPOINT_.219_MILL-MAX_2501: TEST POINT,TURRET,0.094" MTG. HOLE,PCB 0.062" THK; 1: VIO; CLASS: IO; Inventory Qty: 830610; Manufacturer: MILL-MAX; Manufacturer PN: 2501-2-00-80-00-00-07-0; PART_NUMBER: 260-0003
E9 = TEST_POINT_.156_MILL-MAX_2308: TEST POINT,TURRET,0.064" MTG. HOLE,PCB 0.062" THK; 1ST PART FIELD: VP1; CLASS: IO; Inventory Qty: 913405; Manufacturer: MILL-MAX; Manufacturer PN: 2308-2-00-80-00-00-07-0; PART_NUMBER: 260-0004
E10 = TESTPOINT_.219_MILL-MAX_2501: TEST POINT,TURRET,0.094" MTG. HOLE,PCB 0.062" THK; 1: +3.3V; CLASS: IO; Inventory Qty: 830610; Manufacturer: MILL-MAX; Manufacturer PN: 2501-2-00-80-00-00-07-0; PART_NUMBER: 260-0003
E11 = TESTPOINT_.219_MILL-MAX_2501: TEST POINT,TURRET,0.094" MTG. HOLE,PCB 0.062" THK; 1: VAMP+; CLASS: IO; Inventory Qty: 830610; Manufacturer: MILL-MAX; Manufacturer PN: 2501-2-00-80-00-00-07-0; PART_NUMBER: 260-0003
E12 = TESTPOINT_.219_MILL-MAX_2501: TEST POINT,TURRET,0.094" MTG. HOLE,PCB 0.062" THK; 1: VAMP-; CLASS: IO; Inventory Qty: 830610; Manufacturer: MILL-MAX; Manufacturer PN: 2501-2-00-80-00-00-07-0; PART_NUMBER: 260-0003
E13 = TESTPOINT_.219_MILL-MAX_2501: TEST POINT,TURRET,0.094" MTG. HOLE,PCB 0.062" THK; 1: REFIN; CLASS: IO; Inventory Qty: 830610; Manufacturer: MILL-MAX; Manufacturer PN: 2501-2-00-80-00-00-07-0; PART_NUMBER: 260-0003
E14 = TESTPOINT_.219_MILL-MAX_2501: TEST POINT,TURRET,0.094" MTG. HOLE,PCB 0.062" THK; 1: +5V; CLASS: IO; Inventory Qty: 830610; Manufacturer: MILL-MAX; Manufacturer PN: 2501-2-00-80-00-00-07-0; PART_NUMBER: 260-0003
E15 = TEST_POINT_.156_MILL-MAX_2308: TEST POINT,TURRET,0.064" MTG. HOLE,PCB 0.062" THK; 1ST PART FIELD: EN; CLASS: IO; Inventory Qty: 913405; Manufacturer: MILL-MAX; Manufacturer PN: 2308-2-00-80-00-00-07-0; PART_NUMBER: 260-0004
L13 L14 L16 L18 L19 L21-L23 = FERRITEBEAD_ALT1: IND.,33 OHMS@100MHz,FERRITE BEAD,25%,6A,9mOHMS,1206; CLASS: DISCRETE; FPLIST: IND1206N,IND1206L,IND1206M; Inventory Qty: 14164; Manufacturer: MURATA; Manufacturer PN: BLM31PG330SN1L; PART_NUMBER: 200-0178; Package Size: 1206; Tolerance: 25%; VALUE1: 33 OHMS
L17 = IND_ALT: IND.,1.5uH,PWR,SHIELDED,20%,14A,10.52mOHMS,6.56x6.36mm,XEL6030,AEC-Q200; CLASS: DISCRETE; Inventory Qty: 196; Manufacturer: Coilcraft; Manufacturer PN: XEL6030-152MEB; PART_NUMBER: 200-0465; Package Size: 6.56x6.36mm; Tolerance: 20%
Q1 Q2 = 8P_N-CH_TYPE1B: XSTR.,MOSFET,N-CH,PWR TRENCH,30V,18A,SO-8; CLASS: DISCRETE; Inventory Qty: 0; Manufacturer: FAIRCHILD SEMI; PART_NUMBER: 240-0181; Package Type: SO-8; Rated Voltage: 30V
R87 = RES_ALT: RES.,17.8k OHMS,1%,1/10W,0603,AEC-Q200; CLASS: DISCRETE; FPLIST: CR0603N,CR0603L,CR0603M; Inventory Qty: 39192; Manufacturer: NIC; Manufacturer PN: NRC06F1782TRF; PART_NUMBER: 100-0867; Package Size: 0603; Rated Power: 1/10W; Temperature Coefficient: +/-100PPM; Tolerance: 1%
R89 = RES_ALT: RES.,1M OHM,1%,1/10W,0603,AEC-Q200; CLASS: DISCRETE; FPLIST: CR0603N,CR0603L,CR0603M; Inventory Qty: 165918; Manufacturer: VISHAY; Manufacturer PN: CRCW06031M00FKEA; PART_NUMBER: 100-0335; Package Size: 0603; Rated Power: 1/10W; Temperature Coefficient: 100ppm; Tolerance: 1%
R90 = RES_ALT: RES.,215k OHMS,1%,1/10W,0603,AEC-Q200; CLASS: DISCRETE; FPLIST: CR0603N,CR0603L,CR0603M; Inventory Qty: 27708; Manufacturer: NIC; Manufacturer PN: NRC06F2153TRF; PART_NUMBER: 100-2555; Package Size: 0603; Rated Power: 1/10W; Temperature Coefficient: 100ppm; Tolerance: 1%
R95 = RES_ALT: RES.,7.5k OHMS,1%,1/10W,0603,AEC-Q200; CLASS: DISCRETE; FPLIST: CR0603N,CR0603L,CR0603M; Inventory Qty: 44195; Manufacturer: NIC; Manufacturer PN: NRC06F7501TRF; PART_NUMBER: 100-1007; Package Size: 0603; Rated Power: 1/10W; Temperature Coefficient: 100ppm; Tolerance: 1%
R96 = RES_ALT: RES.,4.02k OHMS,1%,1/10W,0603,AEC-Q200; CLASS: DISCRETE; FPLIST: CR0603N,CR0603L,CR0603M; Inventory Qty: 21220; Manufacturer: PANASONIC; Manufacturer PN: ERJ3EKF4021V; PART_NUMBER: 100-2530; Package Size: 0603; Rated Power: 1/10W; Temperature Coefficient: 100ppm; Tolerance: 1%
R106 = RES_ALT: RES.,5.11k OHMS,1%,1/10W,0603; CLASS: DISCRETE; FPLIST: CR0603N,CR0603L,CR0603M; Inventory Qty: 25957; Manufacturer: PANASONIC; Manufacturer PN: ERJ3EKF5111V; PART_NUMBER: 100-2603; Package Size: 0603; Rated Power: 1/10W; Temperature Coefficient: 100ppm/C; Tolerance: 1%
R108 = RES_ALT: RES.,16.9k OHMS,1%,1/10W,0603,AEC-Q200; CLASS: DISCRETE; FPLIST: CR0603N,CR0603L,CR0603M; Inventory Qty: 29972; Manufacturer: NIC; Manufacturer PN: NRC06F1692TRF; PART_NUMBER: 100-2653; Package Size: 0603; Rated Power: 1/10W; Temperature Coefficient: 100ppm; Tolerance: 1%
R110 = RES_ALT: RES.,47.5k OHMS,1%,1/10W,0603; CLASS: DISCRETE; FPLIST: CR0603N,CR0603L,CR0603M; Inventory Qty: 67933; Manufacturer: VISHAY; Manufacturer PN: CRCW060347K5FKEA; PART_NUMBER: 100-2554; Package Size: 0603; Rated Power: 1/10W; Temperature Coefficient: 100ppm/C; Tolerance: 1%
R113 = RES_ALT: RES.,3.3k OHMS,1%,1/10W,0603,AEC-Q200; CLASS: DISCRETE; FPLIST: CR0603N,CR0603L,CR0603M; Inventory Qty: 10760; Manufacturer: VISHAY; Manufacturer PN: CRCW06033K30FKEA; PART_NUMBER: 100-2736; Package Size: 0603; Rated Power: 1/10W; Temperature Coefficient: 100ppm/C; Tolerance: 1%
R115 = RES_ALT: RES.,33.2k OHMS,1%,1/10W,0603; CLASS: DISCRETE; FPLIST: CR0603N,CR0603L,CR0603M; Inventory Qty: 55894; Manufacturer: PANASONIC; Manufacturer PN: ERJ3EKF3322V; PART_NUMBER: 100-2634; Package Size: 0603; Rated Power: 1/10W; Temperature Coefficient: 100ppm; Tolerance: 1%
U15 = LTC4359-DCB_ALT1: IC,4V-80V IDEAL DIODE CONTROLLER,DFN-6DCB-2X3; CLASS: IC; Inventory Qty: 512; Manufacturer: ANALOG DEVICES; Manufacturer PN: LTC4359HDCB#PBF; PART_NUMBER: LTC4359HDCB#PBF; Package Size: DFN-6L; Package Type: DFN-6DCB-2X3; VALUE1: LTC4359HDCB
U16 = LT8640SIV-LQFN24-4X4X0.94: IC,42V, 6A SYNCH. STEP-DOWN REG.,LQFN24-4X4X0.94,SILENT SWITCHER 2; CLASS: IC; Inventory Qty: 0; Manufacturer: ANALOG DEVICES; Manufacturer PN: LT8640SIV#PBF; PART_NUMBER: LT8640SIV#PBF; Package Type: LQFN24-4X4X0.94
U17 = LTM4625-BGA_ALT1: IC,Step-Down DC/DC uModule Reg.,BGA-25; CLASS: IC; Inventory Qty: 0; Manufacturer: LINEAR TECH.; Manufacturer PN: LTM4625IY#PBF; PART_NUMBER: LTM4625IY#PBF; Package Type: BGA-25; VALUE1: LTM4625IY
U18 = LT3093IDD-DFN12DD: IC, ULTRALOW NOISE, ULTRAHIGH PSRR NEGATIVE LINEAR REGULATOR, DFN12DD-3X3; CLASS: IC; Inventory Qty: 0; Manufacturer: ANALOG DEVICES; Manufacturer PN: LT3093IDD#PBF; PART_NUMBER: LT3093IDD#PBF; Package Size: DFN12DD-3X3; Package Type: DFN12DD-3X3
U19 = LT1763-S8-X_ALT3: IC,500mA, LDO uPOWER REGULATOR,SO-8,1.8V; CLASS: IC; Inventory Qty: 35; Manufacturer: LINEAR TECH.; Manufacturer PN: LT1763CS8-1.8#PBF; PART_NUMBER: LT1763CS8-1.8#PBF; Package Size: SO8; Package Type: SO-8; VALUE1: LT1763CS8-1.8
U20-U22 = LT1763-S8-X_ALT3: IC,500mA, LDO uPOWER REGULATOR,SO-8,ADJ.; CLASS: IC; Inventory Qty: 295; Manufacturer: LINEAR TECH.; Manufacturer PN: LT1763CS8#PBF; PART_NUMBER: LT1763CS8#PBF; Package Size: LTC-S8; Package Type: SO-8; VALUE1: LT1763CS8
U23 = LTC6655LNBHMS8-5-MS8: IC,LOW DRIFT PRECISION REFERENCES,MS8,LOW NOISE,0.21ppm; CLASS: IC; Inventory Qty: 35; Manufacturer: ANALOG DEVICES; Manufacturer PN: LTC6655LNBHMS8-5#PBF; PART_NUMBER: LTC6655LNBHMS8-5#PBF; Package Size: MS8; Package Type: MS8
U24 = LT3042-DD_ALT1: IC,PSRR RF Linear Regulator,DFN-10(DD); CLASS: IC; Inventory Qty: 126; Manufacturer: LINEAR TECH.; Manufacturer PN: LT3042EDD#PBF; PART_NUMBER: LT3042EDD#PBF; Package Type: DFN-10(DD); VALUE1: LT3042IDD
JP1 = HDR3X1_E: CONN.,HDR,MALE,1x3,2mm,VERT,ST,THT; CLASS: IO; Inventory Qty: 23833; Manufacturer: Wurth Elektronik; Manufacturer PN: 62000311121; PART_NUMBER: 250-0484
P1 = CON-SAMTEC-SEAM40-10X40: CONN.,BGA SOCKET,10x40,1.27mm,VERT, THT,Open Pin Field, SEAM Series; CLASS: IO; FPLIST: SAMTEC-SEAM-40-02.0-S-10-2-A-K,CON-SEAM-10X40PIN; Inventory Qty: 1512; Manufacturer: SAMTEC; Manufacturer PN: SEAM-40-02.0-S-10-2-A-K-T; PART_NUMBER: 250-0473
U25 = M24C02-DRDW8TP-TSSOP8: IC, MEMORY,EEPROM,I2C,2-Kbit,400kHz,TSSOP8,AEC-Q100; CLASS: IC; Inventory Qty: 1000; Manufacturer: STMICROELECTRONICS; Manufacturer PN: M24C02-DRDW8TP/K; PART_NUMBER: 380-0104; Package Size: TSSOP8; Package Type: TSSOP8
XJP1 = SHUNT_2MM_B: CONN.,SHUNT,FEMALE,2 POS,2mm; CLASS: IO; Inventory Qty: 68064; Manufacturer: Wurth Elektronik; Manufacturer PN: 60800213421; PART_NUMBER: 250-0485

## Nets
+1.8V: C59.2 C60.2 C61.2 C106.1 E5.1 U1.G3(VDD_1.8V) U1.H3(VDD_1.8V) U19.1(OUT) U19.2(SENSE/ADJ)
+3.3V: C1.1 C2.1 C4.1 C5.1 C77.2 C78.2 C80.2 C115.2 E10.1 R2.1 R108.2 U4.5 U5.5 U6.6(~{CLR}) U6.7(~{PR}) U6.8(VCC) U7.5 U18.4(PG) U21.1(OUT) Y1.4(VCC)
+5V: C94.1 C105.1 E14.1 U1.A3(VDD_5V) U1.B3(VDD_5V) U24.9(OUTS) U24.10(OUT)
+12V_FMC: D5.2(A) L23.1
+12V_IN: C85.1 D1.1(C) D4.1(C) D5.1(C) Q2.1(S) Q2.2(S) Q2.3(S) U15.3(SOURCE) U15.4(IN) U17.C5(SVIN) U17.D5(VIN) U17.E5(VIN)
-5V: C90.1 C92.1 R95.2 R138.1 U17.B3(GND) U17.B4(SGND) U17.C3(GND) U17.D3(GND) U17.D4(GND) U17.E3(GND)
GND: C1.2 C2.2 C4.2 C5.2 C7.1 C8.1 C9.1 C10.1 C11.1 C12.1 C14.2 C15.2 C17.1 C20.2 C21.2 C31.1 C36.2 C37.2 C39.1 C42.2 C43.2 C53.1 C57.1 C58.1 C60.1 C61.1 C63.2 C64.2 C65.2 C66.1 C68.1 C69.1 C70.1 C71.1 C73.2 C75.1 C77.1 C78.1 C81.1 C82.1 C83.1 C85.2 C86.2 C89.1 C91.2 C92.2 C94.2 C96.1 C97.2 C98.2 C99.2 C100.2 C101.2 C102.2 C103.2 C104.1 C105.2 C106.2 C107.2 C108.1 C109.1 C110.1 C111.1 C112.1 C113.1 C114.1 C115.1 C120.1 C121.2 C122.2 E7.1 J1.2 J1.3 J1.4 J1.5 J2.2(GND) J2.3(GND) J2.4(GND) J2.5(GND) J3.2(GND) J3.3(GND) J3.4(GND) J3.5(GND) J4.2(GND) J4.3(GND) J4.4(GND) J4.5(GND) J5.2(GND) J5.3(GND) J5.4(GND) J5.5(GND) J6.2 J6.3 J6.4 J6.5 JP1.2 P1.A1(GND) P1.A4(GND) P1.A5(GND) P1.A8(GND) P1.A9(GND) P1.A12(GND) P1.A13(GND) P1.A16(GND) P1.A17(GND) P1.A20(GND) P1.A21(GND) P1.A24(GND) P1.A25(GND) P1.A28(GND) P1.A29(GND) P1.A32(GND) P1.A33(GND) P1.A36(GND) P1.A37(GND) P1.A40(GND) P1.B2(GND) P1.B3(GND) P1.B6(GND) P1.B7(GND) P1.B10(GND) P1.B11(GND) P1.B14(GND) P1.B15(GND) P1.B18(GND) P1.B19(GND) P1.B22(GND) P1.B23(GND) P1.B26(GND) P1.B27(GND) P1.B30(GND) P1.B31(GND) P1.B34(GND) P1.B35(GND) P1.B38(GND) P1.B39(GND) P1.C1(GND) P1.C4(GND) P1.C5(GND) P1.C8(GND) P1.C9(GND) P1.C12(GND) P1.C13(GND) P1.C16(GND) P1.C20(GND) P1.C21(GND) P1.C24(GND) P1.C25(GND) P1.C28(GND) P1.C29(GND) P1.C32(GND) P1.C33(GND) P1.C36(GND) P1.C38(GND) P1.C40(GND) P1.D2(GND) P1.D3(GND) P1.D6(GND) P1.D7(GND) P1.D10(GND) P1.D13(GND) P1.D16(GND) P1.D19(GND) P1.D22(GND) P1.D25(GND) P1.D28(GND) P1.D37(GND) P1.D39(GND) P1.E1(GND) P1.E4(GND) P1.E5(GND) P1.E8(GND) P1.E11(GND) P1.E14(GND) P1.E17(GND) P1.E20(GND) P1.E23(GND) P1.E26(GND) P1.E29(GND) P1.E32(GND) P1.E35(GND) P1.E38(GND) P1.E40(GND) P1.F2(GND) P1.F3(GND) P1.F6(GND) P1.F9(GND) P1.F12(GND) P1.F15(GND) P1.F18(GND) P1.F21(GND) P1.F24(GND) P1.F27(GND) P1.F30(GND) P1.F33(GND) P1.F36(GND) P1.F39(GND) P1.G1(GND) P1.G4(GND) P1.G5(GND) P1.G8(GND) P1.G11(GND) P1.G14(GND) P1.G17(GND) P1.G20(GND) P1.G23(GND) P1.G26(GND) P1.G29(GND) P1.G32(GND) P1.G35(GND) P1.G38(GND) P1.G40(GND) P1.H2(PRSNT_M2C_N) P1.H3(GND) P1.H6(GND) P1.H9(GND) P1.H12(GND) P1.H15(GND) P1.H18(GND) P1.H21(GND) P1.H24(GND) P1.H27(GND) P1.H30(GND) P1.H33(GND) P1.H36(GND) P1.H39(GND) P1.J1(GND) P1.J4(GND) P1.J5(GND) P1.J8(GND) P1.J11(GND) P1.J14(GND) P1.J17(GND) P1.J20(GND) P1.J23(GND) P1.J26(GND) P1.J29(GND) P1.J32(GND) P1.J35(GND) P1.J38(GND) P1.J40(GND) P1.K2(GND) P1.K3(GND) P1.K6(GND) P1.K9(GND) P1.K12(GND) P1.K15(GND) P1.K18(GND) P1.K21(GND) P1.K24(GND) P1.K27(GND) P1.K30(GND) P1.K33(GND) P1.K36(GND) P1.K39(GND) R4.2 R5.2 R17.2 R27.2 R84.2 R87.2 R88.2 R90.1 R107.1 R109.1 R111.1 R113.2 R114.1 R115.1 R117.1 R133.1 R134.1 R135.2 U1.A1(GND) U1.A4(GND) U1.A5(GND) U1.B2(GND) U1.B4(GND) U1.B5(GND) U1.B6(IOGND) U1.B7(IOGND) U1.C2(GND) U1.C3(GND) U1.C4(GND) U1.C5(GND) U1.C6(IOGND) U1.D1(GND) U1.D4(GND) U1.D5(GND) U1.D6(IOGND) U1.E1(GND) U1.E4(GND) U1.E5(GND) U1.E6(IOGND) U1.E7(IOGND) U1.F2(GND) U1.F3(GND) U1.F4(GND) U1.F5(GND) U1.F6(IOGND) U1.G2(GND) U1.G4(GND) U1.G5(GND) U1.G6(IOGND) U1.H1(GND) U1.H2(GND) U1.H4(GND) U1.H8(IOGND) U2.16(DGND) U3.16(DGND) U4.3 U5.3 U6.4(GND) U7.3 U8.2(T/~{R}) U8.11(GND) U8.12(GND) U8.13(GND) U8.22(~{OE}) U8.25(EP) U9.11(GND) U9.12(GND) U9.13(GND) U9.22(~{OE}) U9.25(EP) U10.5(GND) U10.6(GND) U10.7(OE) U16.3(GND) U16.16(GND) U16.22(GND) U16.25(EP-GND) U16.26(EP-GND) U16.27(EP-GND) U16.28(EP-GND) U17.C1(VOUT) U17.D1(VOUT) U17.D2(VOUT) U17.E1(VOUT) U17.E2(VOUT) U18.9(GND) U19.3(GND) U19.6(GND) U19.7(GND) U20.3(GND) U20.6(GND) U20.7(GND) U21.3(GND) U21.6(GND) U21.7(GND) U22.3(GND) U22.6(GND) U22.7(GND) U23.3(GND) U23.4(GND) U23.5(GND) U23.8(GND) U24.5(ILIM) U24.8(GND) U24.11(EP) U25.3(E2) U25.4(VSS) Y1.2(GND)
3.3_AUX: C96.2 P1.D32(3P3VAUX) R97.1 R98.1 R99.1 U25.8(VCC)
/CS: U1.H5(\~{CS}) U8.10(A7)
/RESET: U1.A7(\~{RESET}) U8.4(A1)
A0: P1.C34(GA0) U25.2(E1)
A1: P1.D35(GA1) U25.1(E0)
BUSY: U1.E8(BUSY) U10.2(A0)
BUSY_FMC: P1.C22(LA18_P_CC) U10.9(B0)
CLK: P1.H4(CLK0_M2C_P) R3.2
CNV: U1.A6(CNV) U8.3(A0)
CNV_FMC: P1.D8(LA01_P_CC) U7.2
CS_FMC: P1.G7(LA00_N_CC) U8.14(B7)
EN: E15.1(A) P1.D1(PG_C2M) R117.2 R132.1 U15.5(~{SHDN}) U18.3(EN/UV) U19.5(~{SHDN}) U20.5(~{SHDN}) U21.5(~{SHDN}) U22.5(~{SHDN}) U23.1(~{SHDN}) U24.3(EN/UV)
IN0+: C98.1 R102.1 U1.B1(IN0+)
IN0-: C97.1 R100.1 U1.C1(IN0-)
IN1+: C100.1 R105.1 U1.F1(IN1+)
IN1-: C99.1 R103.1 U1.G1(IN1-)
IN_A+: R10.1 R28.1 R120.2
IN_A-: R12.1 R43.1 R121.1
IN_B+: R20.1 R57.1 R124.2
IN_B-: R22.1 R72.1 R125.1
OUT_A+: R13.2 R119.2
OUT_A-: R11.2 R122.2
OUT_B+: R23.2 R123.2
OUT_B-: R21.2 R126.2
REF: E16.1(A) R118.2 U1.D2(REF) U1.D3(REF) U1.E2(REF) U1.E3(REF)
REFIN: C95.2 C120.2 E13.1 R15.1 R25.1 R32.1 R96.1 R118.1 R136.2 R137.1
RESET_FMC: P1.D9(LA01_N_CC) U8.20(B1)
SCK: U1.H7(SCK) U8.8(A5) U10.3(A1)
SCK_FMC: P1.G6(LA00_P_CC) U8.16(B5)
SCK_OUT_FMC: P1.D20(LA17_P_CC) U10.8(B1)
SCL: P1.C30(SCL) R97.2 U25.6(SCL)
SDA: P1.C31(SDA) R98.2 U25.5(SDA)
SDI: U1.H6(SDI) U8.9(A6)
SDI_FMC: P1.C11(LA06_N) U8.15(B6)
SDO0: U1.D8(SDO0) U9.6(A3)
SDO0_FMC: P1.H7(LA02_P) U9.18(B3)
SDO1: U1.C8(SDO1) U9.4(A1)
SDO1_FMC: P1.H8(LA02_N) U9.20(B1)
SDO2: U1.D7(SDO2) U9.5(A2)
SDO2_FMC: P1.G9(LA03_P) U9.19(B2)
SDO3: U1.C7(SDO3) U9.3(A0)
SDO3_FMC: P1.G10(LA03_N) U9.21(B0)
SDO4: U1.F8(SDO4) U9.8(A5)
SDO4_FMC: P1.H10(LA04_P) U9.16(B5)
SDO5: U1.G8(SDO5) U9.10(A7)
SDO5_FMC: P1.H11(LA04_N) U9.14(B7)
SDO6: U1.F7(SDO6) U9.7(A4)
SDO6_FMC: P1.D11(LA05_P) U9.17(B4)
SDO7: U1.G7(SDO7) U9.9(A6)
SDO7_FMC: P1.D12(LA05_N) U9.15(B6)
VADJ: C8.2 C10.2 C12.2 P1.G39(VADJ) P1.H40(VADJ) U8.23(VCCB) U8.24(VCCB) U9.23(VCCB) U9.24(VCCB) U10.10(VCCB)
VAMP+: C13.1 C14.1 C15.1 C35.1 C36.1 C37.1 C82.2 C83.2 C84.2 C110.2 C113.2 E11.1 R110.2 U2.5(MODE) U2.6(+VS) U2.7(+VS) U2.8(+VCLAMP) U2.12(~{DISABLE}) U3.5(MODE) U3.6(+VS) U3.7(+VS) U3.8(+VCLAMP) U3.12(~{DISABLE}) U11.8(PWR) U12.8(PWR) U22.1(OUT)
VAMP-: C13.2 C20.1 C21.1 C35.2 C42.1 C43.1 C101.1 C109.2 C112.2 E12.1 R113.1 U2.13(-VCLAMP) U2.14(-VS) U2.15(-VS) U2.17(-VS) U3.13(-VCLAMP) U3.14(-VS) U3.15(-VS) U3.17(-VS) U11.4(GND) U12.4(GND) U18.10(OUTS) U18.11(OUT) U18.12(OUT)
VIO: C7.2 C9.2 C11.2 C67.2 C68.2 C69.2 C107.1 E8.1 R106.2 U1.A8(VIO) U1.B8(VIO) U8.1(VCCA) U9.1(VCCA) U9.2(T/~{R}) U10.1(VCCA) U10.4(TR) U20.1(OUT)
N18004608: JP1.1 R99.2 U25.7(~{WC})
N21488838: C116.1 R8.1 R10.2 U2.2(+IN)
N21489335: C117.2 R12.2 R14.2 U2.3(-IN)
N21490034: C116.2 R8.2 R11.1 U2.11(-OUT)
N21490037: C117.1 R13.1 R14.1 U2.10(+OUT)
N21490536: C111.2 R15.2 R17.1 U2.9(VOCM)
N21519233: R31.2 U11.3(+IN)
N21519504: J2.1 R30.1
N21519575: C17.2 R30.2 R31.1 R101.1 R120.1
N21519757: R28.2 R29.1 R127.1
N21519775: R33.1 R127.2 U11.1(VOUT) U11.2(-IN)
N21519778: R29.2 R33.2 R100.2 R119.1
N21521427: C118.1 R18.1 R20.2 U3.2(+IN)
N21521431: C118.2 R18.2 R21.1 U3.11(-OUT)
N21521459: C119.2 R22.2 R24.2 U3.3(-IN)
N21521463: C119.1 R23.1 R24.1 U3.10(+OUT)
N21521479: C114.2 R25.2 R27.1 U3.9(VOCM)
N21529195: C31.2 R46.2 R47.1 R101.2 R121.2
N21529197: R43.2 R44.1 R128.2
N21529199: R44.2 R49.2 R102.2 R122.1
N21529394: J3.1 R46.1
N21529402: R47.2 U11.5(+IN)
N21529410: R49.1 R128.1 U11.6(-IN) U11.7(VOUT)
N21536561: R57.2 R58.1 R129.1
N21536563: R58.2 R62.2 R103.2 R123.1
N21536758: J5.1 R77.1
N21536760: C39.2 R59.2 R60.1 R104.1 R124.1
N21536770: R60.2 U12.3(+IN)
N21536778: R62.1 R129.2 U12.1(VOUT) U12.2(-IN)
N21537046: C53.2 R77.2 R78.1 R104.2 R125.2
N21537050: R72.2 R73.1 R130.2
N21537052: R73.2 R75.2 R105.2 R126.1
N21537213: R75.1 R130.1 U12.6(-IN) U12.7(VOUT)
N21537291: J4.1 R59.1
N21537301: R78.2 U12.5(+IN)
N21586957: C3.2 R2.2 R5.1 U4.2
N21586971: C3.1 J1.1 R4.1 R55.2
N21586981: R1.2 U4.4 U5.2
N21587374: R1.1 U6.1(CP)
N21587390: R6.2 U6.2(D)
N21587488: R7.2 U6.3(~{Q})
N21597374: R3.1 U5.4
N21613581: R7.1 U8.21(B0)
N21627477: R6.1 U7.4
N21816768: C58.2 L13.1 U19.8(IN)
N21816830: C59.1 U19.4(BYP)
N21817212: C64.1 C65.1 C70.2 C71.2 D3.2(ANODE) L14.1 U16.5(VIN) U16.6(VIN) U16.13(VIN) U16.14(VIN) U16.17(EN)
N21817681: C62.1 C63.1 L14.2 Q2.5(D) Q2.6(D) Q2.7(D) Q2.8(D) R86.1 U15.1(OUT)
N21817744: C62.2 D2.1(C) R88.1 U15.6(VSS) U15.7(EP)
N21891459: D1.2(A) D2.2(A)
N21891547: Q2.4(G) U15.2(GATE)
N21891932: C72.2 C73.1 L17.2 Q1.1(S) Q1.2(S) Q1.3(S) R89.1 U16.1(BIAS)
N21892100: Q1.4(G) R86.2
N21903199: C66.2 L16.1 U20.8(IN)
N21903263: C67.1 U20.4(BYP)
N21903528: C75.2 L18.1 U21.8(IN)
N21903592: C80.1 U21.4(BYP)
N21904347: C81.2 L19.1 U22.8(IN)
N21904411: C84.1 U22.4(BYP)
N21909887: C57.2 E9.1(A) L13.2 L16.2 L18.2 L19.2 L21.2 L22.2 Q1.5(D) Q1.6(D) Q1.7(D) Q1.8(D)
N21914202: D4.2(A) E6.1
N21943303: R131.1 U17.C4(MODE)
N21945033: C121.1 R95.1 U17.B1(FB)
N21946370: R131.2 U17.E4(INTVCC)
N21959014: C86.1 R139.2 U18.1(IN) U18.2(IN) U18.5(PGFB) U18.13(EP/IN)
N21963658: C89.2 L21.1 U23.2(VIN)
N21963927: C91.1 R136.1 U23.7(VOUT_F)
N21965405: C104.2 L22.1 U24.1(IN) U24.2(IN) U24.6(PGFB)
N21965436: C95.1 R96.2 U24.7(SET)
N21975912: L23.2 P1.C35(12P0V) P1.C37(12P0V)
N22020514: R106.1 R107.2 U20.2(SENSE/ADJ)
N22023635: R108.1 R109.2 U21.2(SENSE/ADJ)
N22024125: R110.1 R111.2 U22.2(SENSE/ADJ)
N22025827: C102.1 U23.6(NR)
N22034293: C103.1 R115.2 U18.8(SET)
N22038333: R114.2 U18.6(ILIM)
N22075054: P1.D30(TDI) P1.D31(TDO)
N22136611: U16.2(INTVCC) U16.20(SYNC/MODE)
N22137698: R87.1 U16.18(RT)
N22140085: L17.1 U16.8(SW) U16.9(SW) U16.10(SW) U16.11(SW) U16.12(SW)
N22141300: D3.1(CATHODE) U16.23(PG)
N22141357: C72.1 R89.2 R90.2 U16.24(FB)
N22172202: C108.2 R32.2 U1.A2(REFIN)
N22268584: R55.1 Y1.3(OUT)
N22282754: R84.1 Y1.1(E/D)
N22300588: C90.2 U17.A2(TRACK/SS)
N22302000: R132.2 U17.A3(RUN)
N22302369: R133.2 U17.A5(CLKIN)
N22302387: R134.2 U17.A4(FREQ)
N22303280: R135.1 U17.B5(CLKOUT)
N22308605: J6.1 R137.2
N22314409: C122.1 R138.2 R139.1

Not connected (* = marked no-connect by the designer): JP1 3*; P1 A2(DP1_M2C_P)* A3(DP1_M2C_N)* A6(DP2_M2C_P)* A7(DP2_M2C_N)* A10(DP3_M2C_P)* A11(DP3_M2C_N)* A14(DP4_M2C_P)* A15(DP4_M2C_N)* A18(DP5_M2C_P)* A19(DP5_M2C_N)* A22(DP1_C2M_P)* A23(DP1_C2M_N)* A26(DP2_C2M_P)* A27(DP2_C2M_N)* A30(DP3_C2M_P)* A31(DP3_C2M_N)* A34(DP4_C2M_P)* A35(DP4_C2M_N)* A38(DP5_C2M_P)* A39(DP5_C2M_N)* B1(RES1)* B4(DP9_M2C_P)* B5(DP9_M2C_N)* B8(DP8_M2C_P)* B9(DP8_M2C_N)* B12(DP7_M2C_P)* B13(DP7_M2C_N)* B16(DP6_M2C_P)* B17(DP6_M2C_N)* B20(GBTCLK1_M2C_P)* B21(GBTCLK1_M2C_N)* B24(DP9_C2M_P)* B25(DP9_C2M_N)* B28(DP8_C2M_P)* B29(DP8_C2M_N)* B32(DP7_C2M_P)* B33(DP7_C2M_N)* B36(DP6_C2M_P)* B37(DP6_C2M_N)* B40(RES0)* C2(DP0_C2M_P)* C3(DP0_C2M_N)* C6(DP0_M2C_P)* C7(DP0_M2C_N)* C10(LA06_P)* C14(LA10_P)* C15(LA10_N)* C17(GND)* C18(LA14_P)* C19(LA14_N)* C23(LA18_N_CC)* C26(LA27_P)* C27(LA27_N)* C39(3P3V)* D4(GBTCLK0_M2C_P)* D5(GBTCLK0_M2C_N)* D14(LA09_P)* D15(LA09_N)* D17(LA13_P)* D18(LA13_N)* D21(LA17_N_CC)* D23(LA23_P)* D24(LA23_N)* D26(LA26_P)* D27(LA26_N)* D29(TCK)* D33(TMS)* D34(TRST_N)* D36(3P3V)* D38(3P3V)* D40(3P3V)* E2(HA01_P_CC)* E3(HA01_N_CC)* E6(HA05_P)* E7(HA05_N)* E9(HA09_P)* E10(HA09_N)* E12(HA13_P)* E13(HA13_N)* E15(HA16_P)* E16(HA16_N)* E18(HA20_P)* E19(HA20_N)* E21(HB03_P)* E22(HB03_N)* E24(HB05_P)* E25(HB05_N)* E27(HB09_P)* E28(HB09_N)* E30(HB13_P)* E31(HB13_N)* E33(HB21_P)* E34(HB21_N)* E36(HB20_P)* E37(HB20_N)* E39(VADJ)* F1(PG_M2C)* F4(HA00_P_CC)* F5(HA00_N_CC)* F7(HA04_P)* F8(HA04_N)* F10(HA08_P)* F11(HA08_N)* F13(HA12_P)* F14(HA12_N)* F16(HA15_P)* F17(HA15_N)* F19(HA19_P)* F20(HA19_N)* F22(HB02_P)* F23(HB02_N)* F25(HB04_P)* F26(HB04_N)* F28(HB08_P)* F29(HB08_N)* F31(HB12_P)* F32(HB12_N)* F34(HB16_P)* F35(HB16_N)* F37(HB19_P)* F38(HB19_N)* F40(VADJ)* G2(CLK0_C2M_P)* G3(CLK0_C2M_N)* G12(LA08_P)* G13(LA08_N)* G15(LA12_P)* G16(LA12_N)* G18(LA16_P)* G19(LA16_N)* G21(LA20_P)* G22(LA20_N)* G24(LA22_P)* G25(LA22_N)* G27(LA25_P)* G28(LA25_N)* G30(LA29_P)* G31(LA29_N)* G33(LA31_P)* G34(LA31_N)* G36(LA33_P)* G37(LA33_N)* H1(VREF_A_M2C)* H5(CLK0_M2C_N)* H13(LA07_P)* H14(LA07_N)* H16(LA11_P)* H17(LA11_N)* H19(LA15_P)* H20(LA15_N)* H22(LA19_P)* H23(LA19_N)* H25(LA21_P)* H26(LA21_N)* H28(LA24_P)* H29(LA24_N)* H31(LA28_P)* H32(LA28_N)* H34(LA30_P)* H35(LA30_N)* H37(LA32_P)* H38(LA32_N)* J2(CLK1_C2M_P)* J3(CLK1_C2M_N)* J6(HA03_P)* J7(HA03_N)* J9(HA07_P)* J10(HA07_N)* J12(HA11_P)* J13(HA11_N)* J15(HA14_P)* J16(HA14_N)* J18(HA18_P)* J19(HA18_N)* J21(HA22_P)* J22(HA22_N)* J24(HB01_P)* J25(HB01_N)* J27(PB07_P)* J28(HB07_N)* J30(HB11_P)* J31(HB11_N)* J33(HB15_P)* J34(HB15_N)* J36(HB18_P)* J37(HB18_N)* J39(VIO_B_M2C)* K1(VREF_B_M2C)* K4(CLK1_M2C_P)* K5(CLK1_M2C_N)* K7(HA02_P)* K8(HA02_N)* K10(HA06_P)* K11(HA06_N)* K13(HA10_P)* K14(HA10_N)* K16(HA17_P_CC)* K17(HA17_N_CC)* K19(HA21_P)* K20(HA21_N)* K22(HA23_P)* K23(HA23_N)* K25(HB00_P_CC)* K26(HB00_N_CC)* K28(HB06_P_CC)* K29(HB06_N_CC)* K31(HB10_P)* K32(HB10_N)* K34(HB14_P)* K35(HB14_N)* K37(HB17_P_CC)* K38(HB17_N_CC)* K40(VIO_B_M2C)*; U2 1(-FB)* 4(+FB)*; U3 1(-FB)* 4(+FB)*; U6 5(Q)*; U8 5(A2)* 6(A3)* 7(A4)* 17(B4)* 18(B3)* 19(B2)*; U16 4(NC)* 7(BST)* 15(NC)* 19(CLKOUT)* 21(TR/SS)*; U17 A1(COMP)* B2(PHMODE)* C2(PGOOD)*; U18 7(VIOC)*; U24 4(PG)*

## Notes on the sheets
sheet 1
- REVISION HISTORY
- ECO
- REV
- DESCRIPTION
- APPROVED
- DATE
- 3
- 3RD PROTOTYPE
- CLARENCE M.
- 12-09-20
- CLK IN
- 3.3VPP
- 100MHz MAX
- [3.]
- NOTE: UNLESS OTHERWISE SPECIFIED:
- 1.  ALL RESISTORS AND CAPACITORS ARE 0603
- 2.  INSTALL SHUNTS AS SHOWN.
- [3.]  ASSEMBLY TABLE:
- ASSY
- EVAL. ORDER NUMBER
- SUFFIX
- -BIT
- MSPS
- (U1)
- A
- EVAL-AD4630-24FMCZ
- 30-24
- 24
- 2
- B
- EVAL-AD4630-20FMCZ
- 30-20
- 20
- 2
- C
- EVAL-AD4630-16FMCZ
- 30-16
- 16
- 2
- D
- EVAL-AD4631-24FMCZ
- 31-24
- 24
- 1
- E
- EVAL-AD4631-20FMCZ
- 31-20
- 20
- 1
- F
- EVAL-AD4631-16FMCZ
- 31-16
- 16
- 1
- G
- EVAL-AD4632-24FMCZ
- 32-24
- 24
- 0.5
- H
- EVAL-AD4632-20FMCZ
- 32-20
- 20
- 0.5
- I
- EVAL-AD4632-16FMCZ
- 32-16
- 16
- 0.5
sheet 2
- NOTE: UNLESS OTHERWISE SPECIFIED:
- 1.  ALL RESISTORS AND CAPACITORS ON THIS PAGE ARE 0402.
sheet 3
- FERRITE BEAD
- FERRITE BEAD
- FERRITE BEAD
- POWER
- FAULT
- FERRITE BEAD
- FERRITE BEAD
- FERRITE BEAD
- EXT REF
- FERRITE BEAD
sheet 4
- FRAME CLOCK B
- DATA CLOCK
- FRAME CLOCK A
- FERRITE BEAD
- WC
- EN
- DIS
